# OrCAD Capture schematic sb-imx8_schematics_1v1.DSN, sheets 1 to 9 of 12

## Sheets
1 11. PCIe x1: size A; title: 11. PCIe x1; rev: 1.1; note: 8010055003
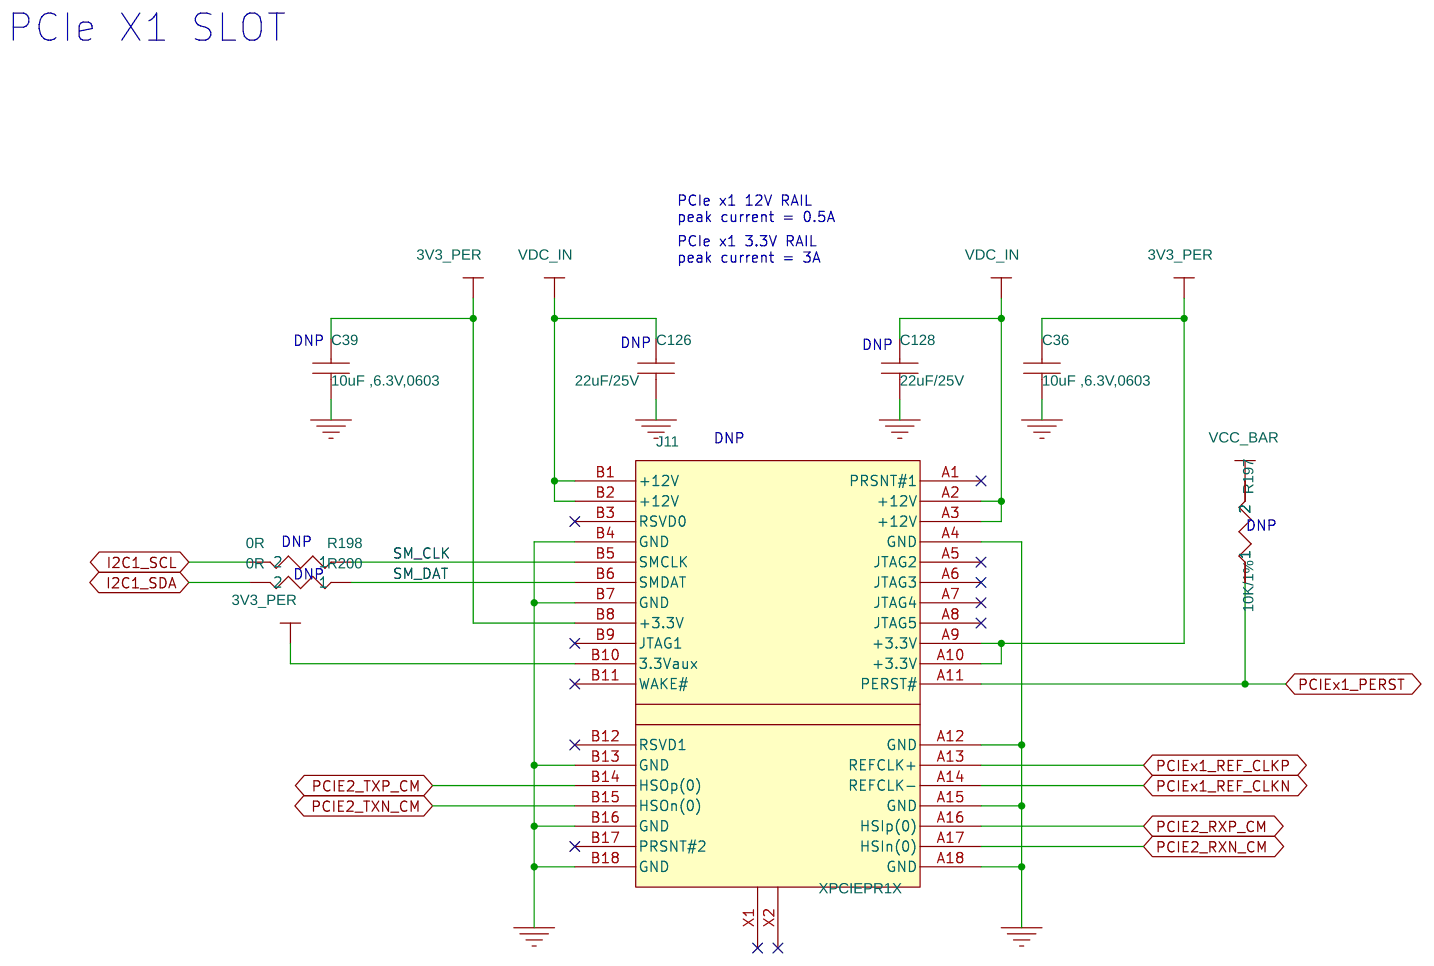
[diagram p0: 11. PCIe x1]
2 10. LVDS LCD: size A3; title: 10. LVDS LCD
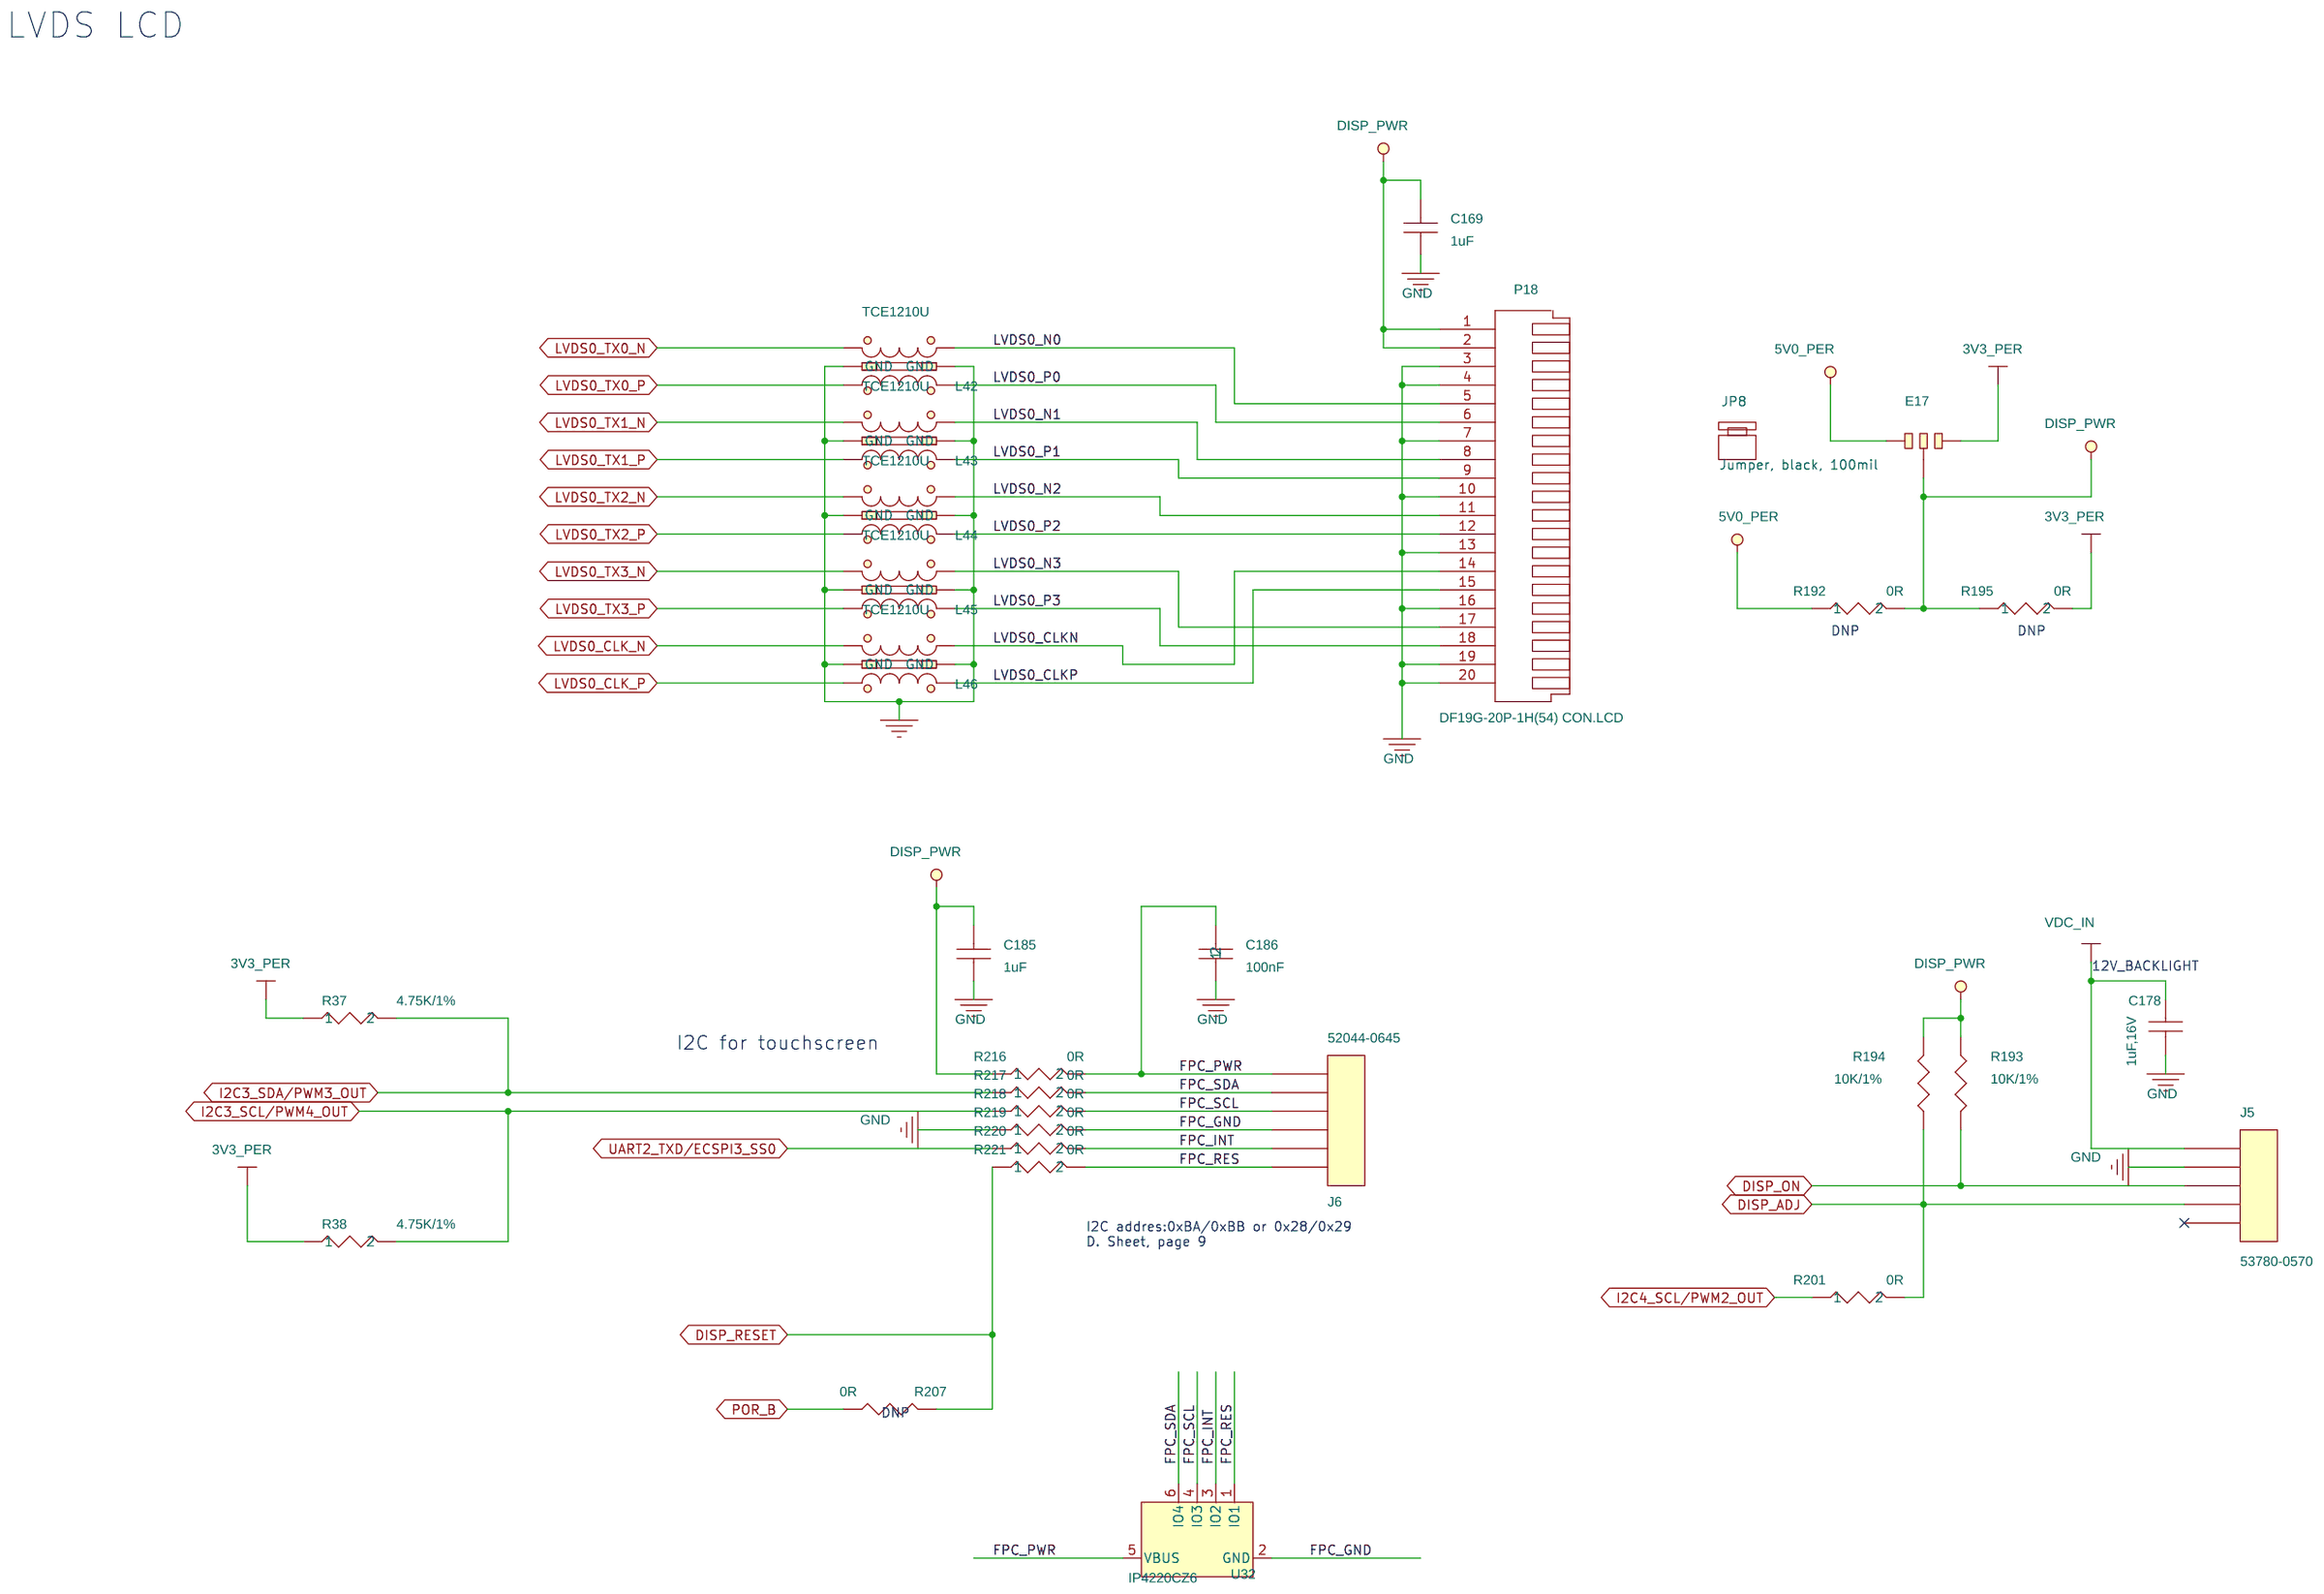
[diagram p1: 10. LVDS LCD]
3 12. Mechanics: size B; title: 12. Mechanics; note: 8000064001
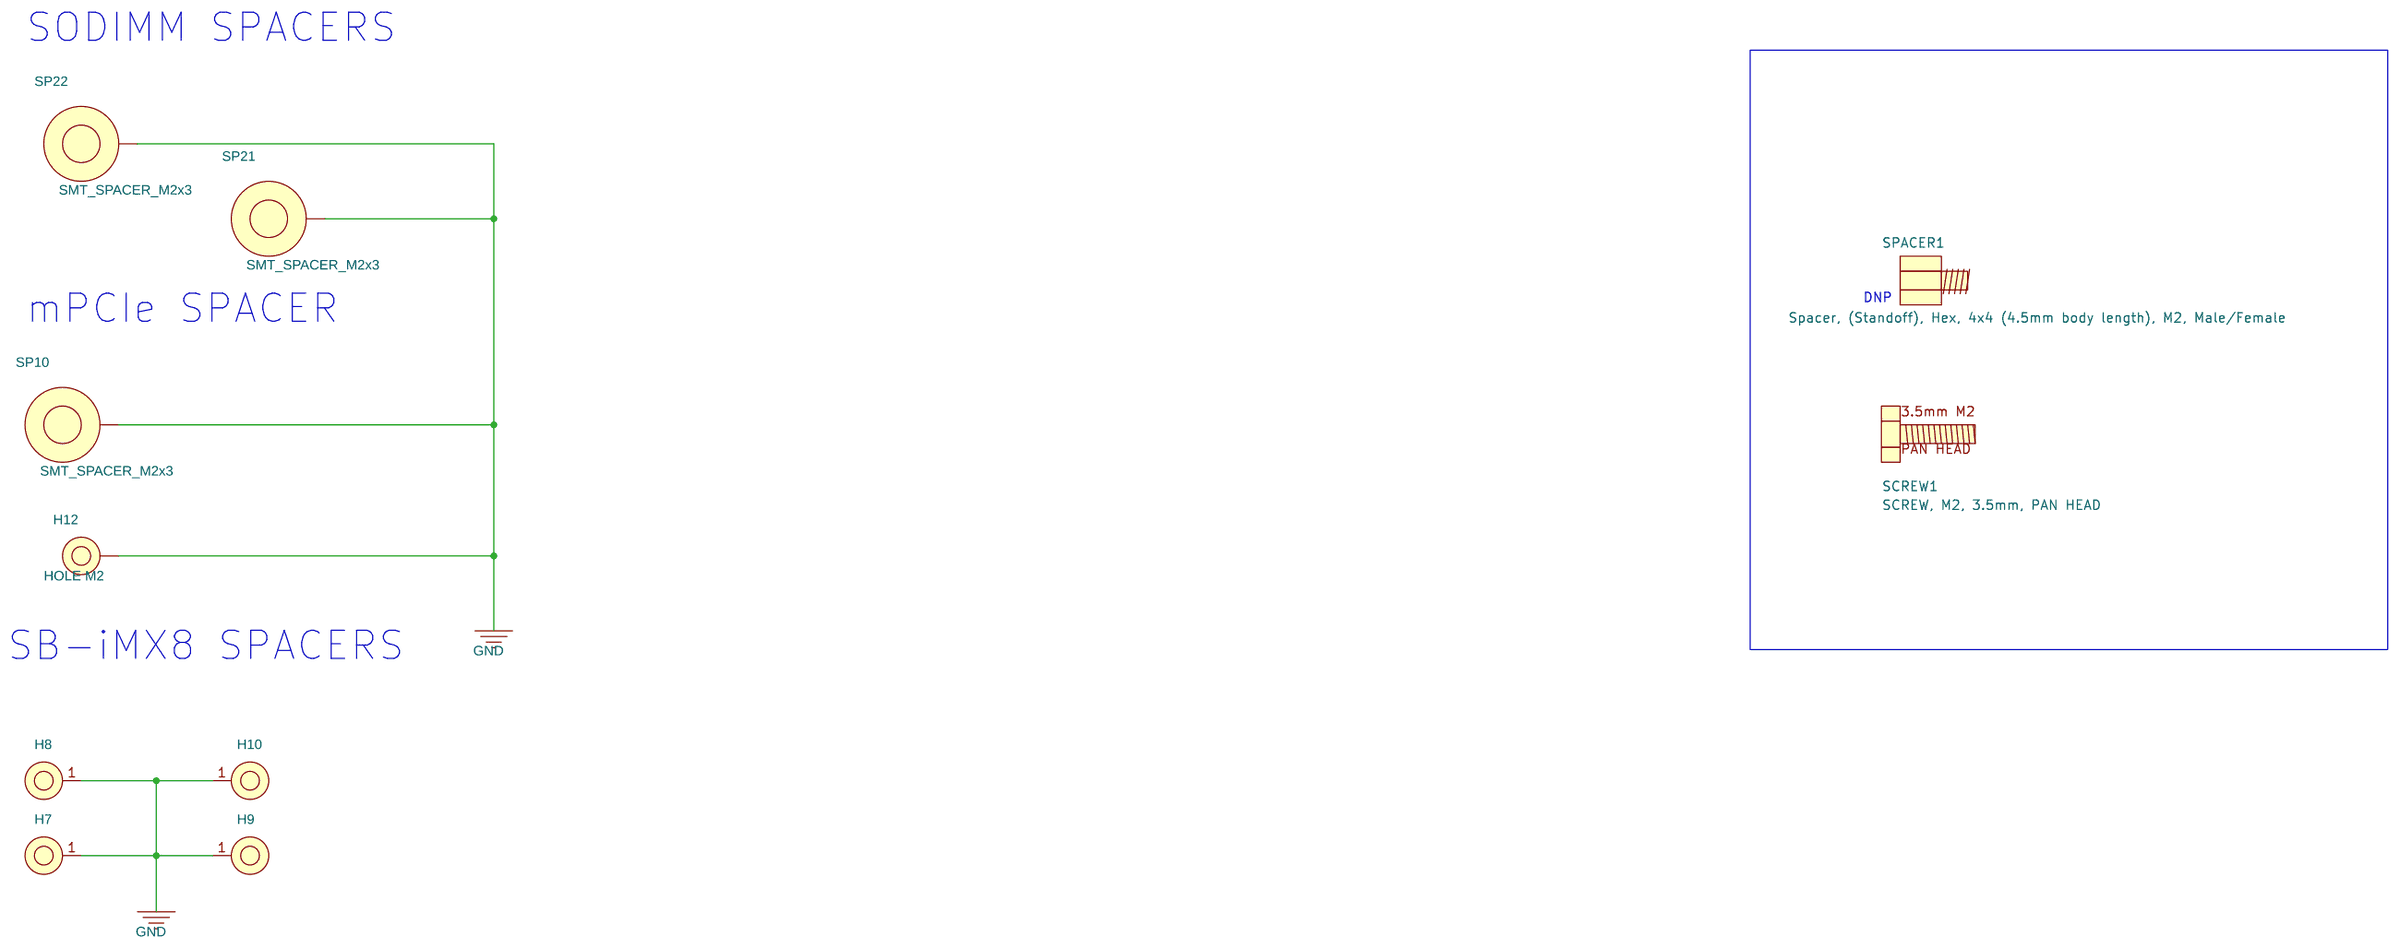
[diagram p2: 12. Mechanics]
4 01. BLOCK DIAGRAM: size C; title: 01. BLOCK DIAGRAM
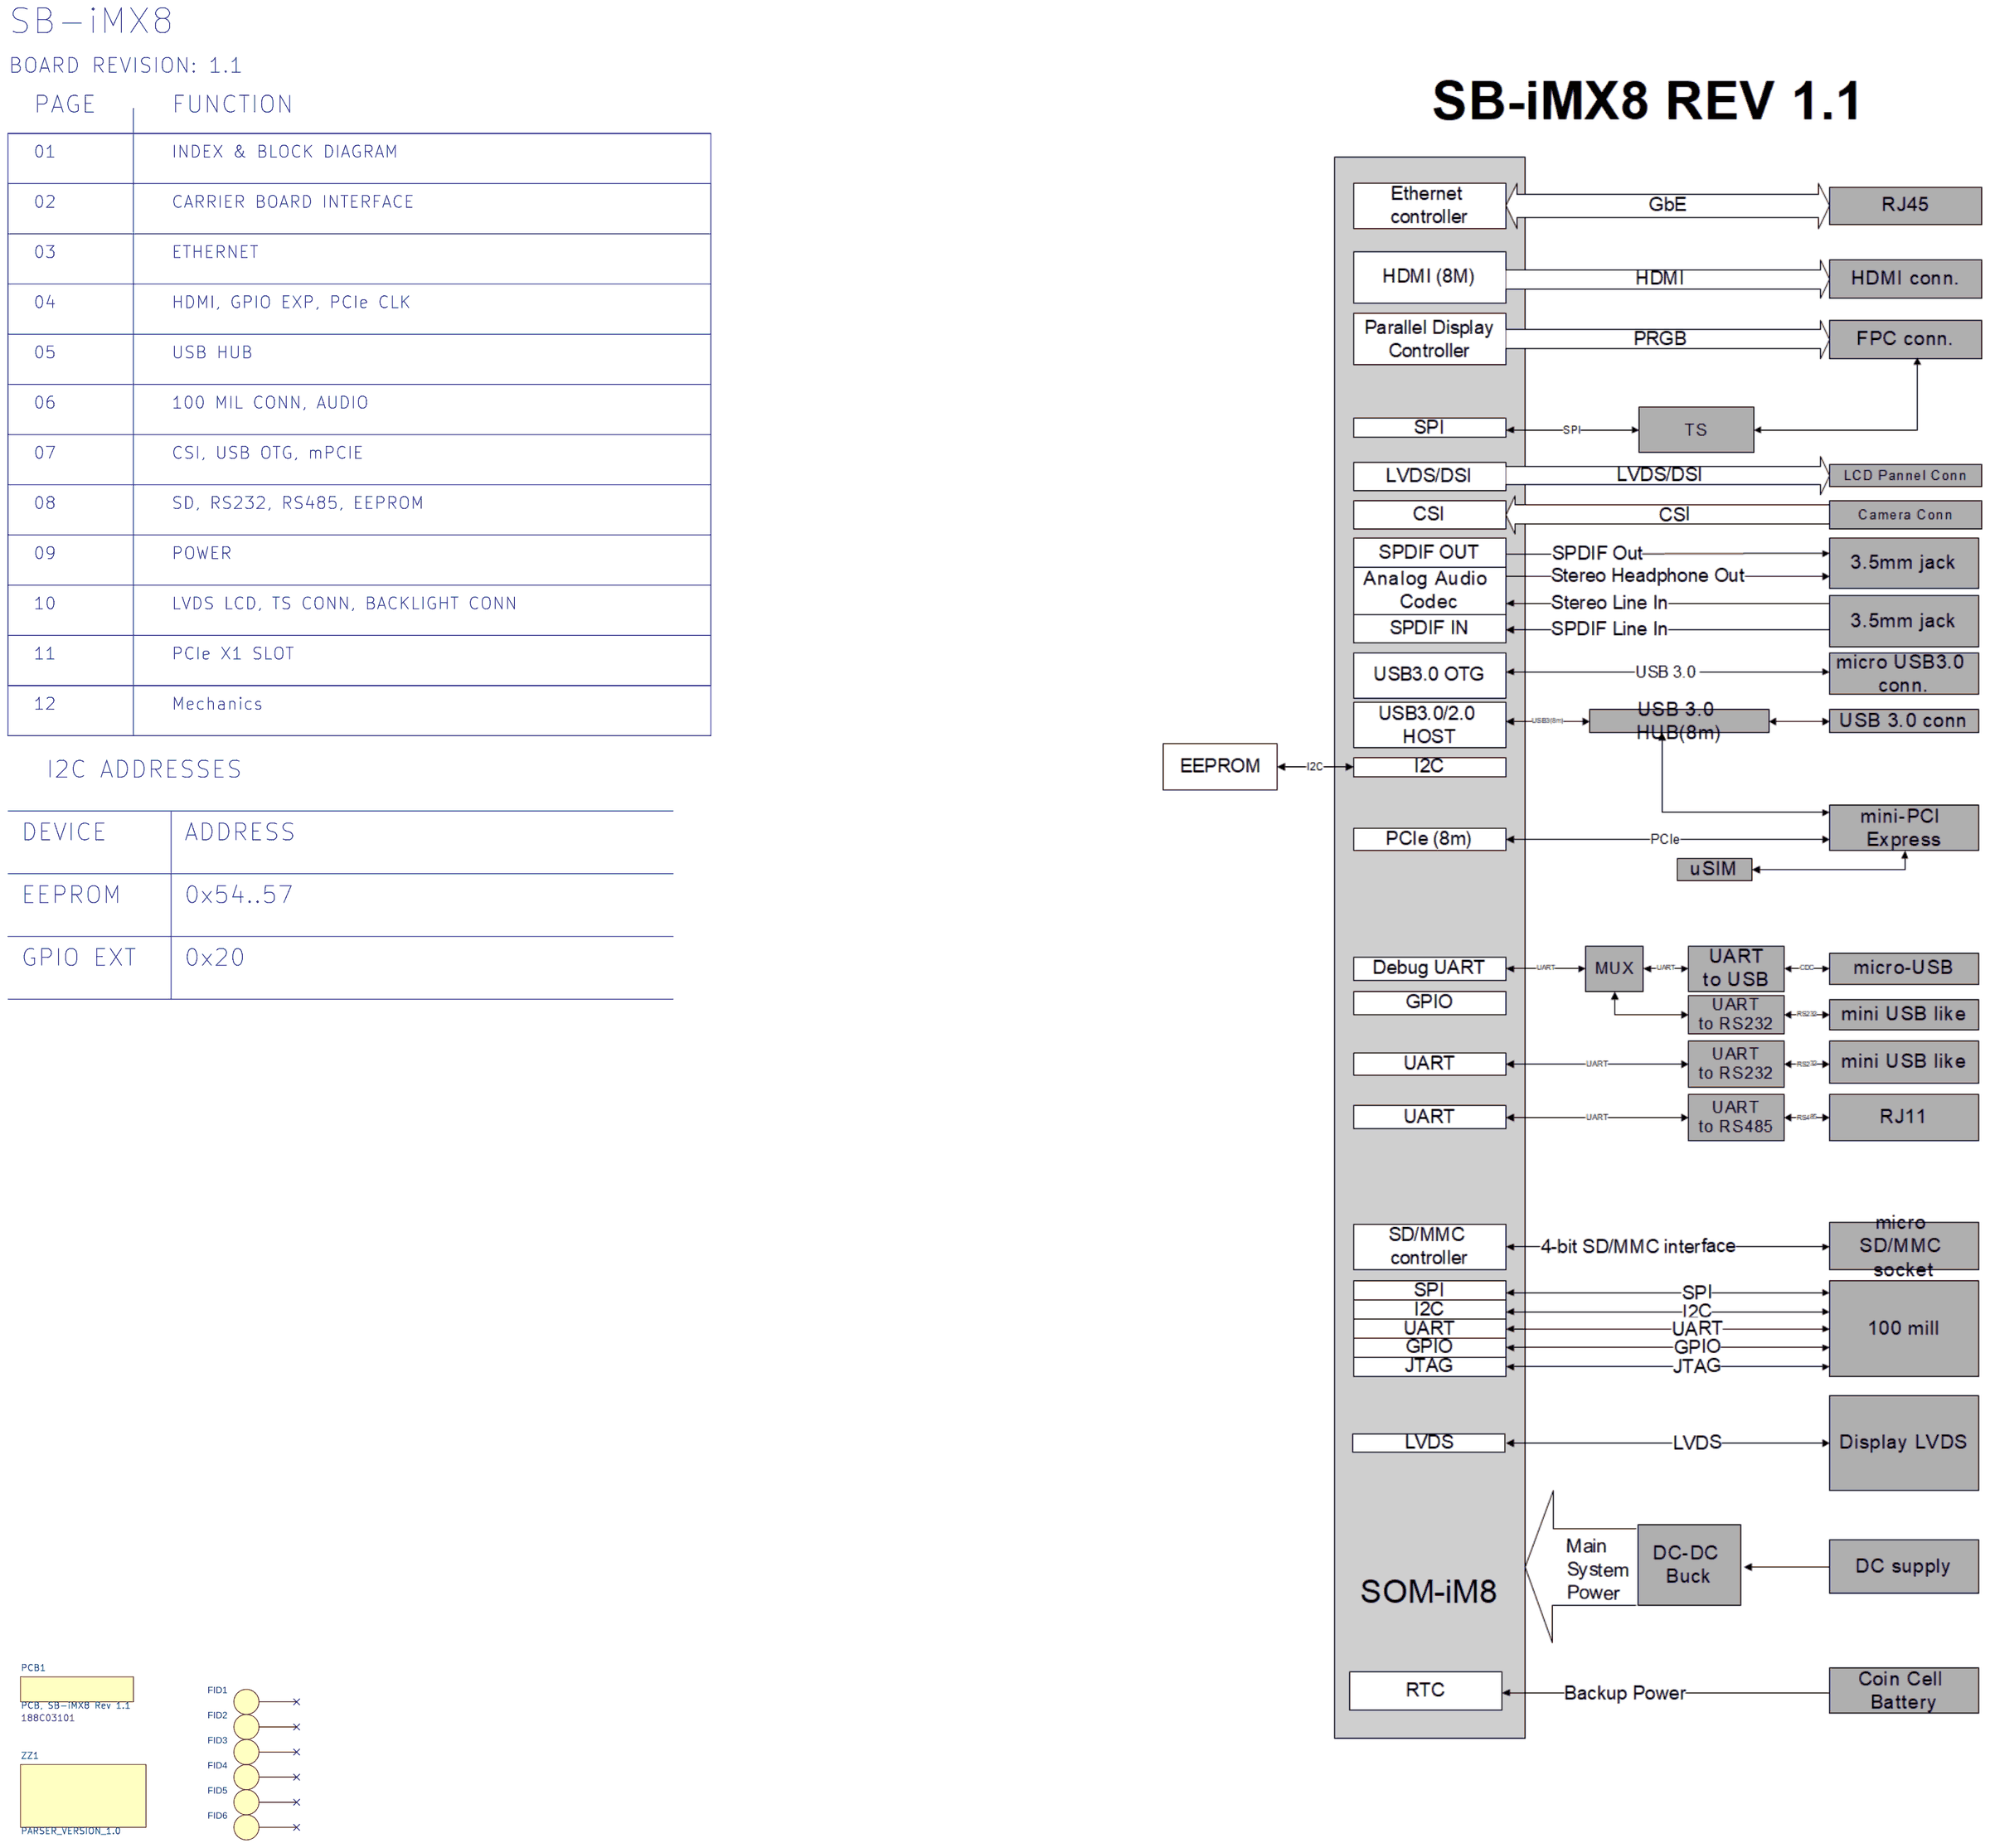
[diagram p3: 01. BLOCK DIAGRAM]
5 02. SODIMM: size C; title: 02. SODIMM; note: 8000064001
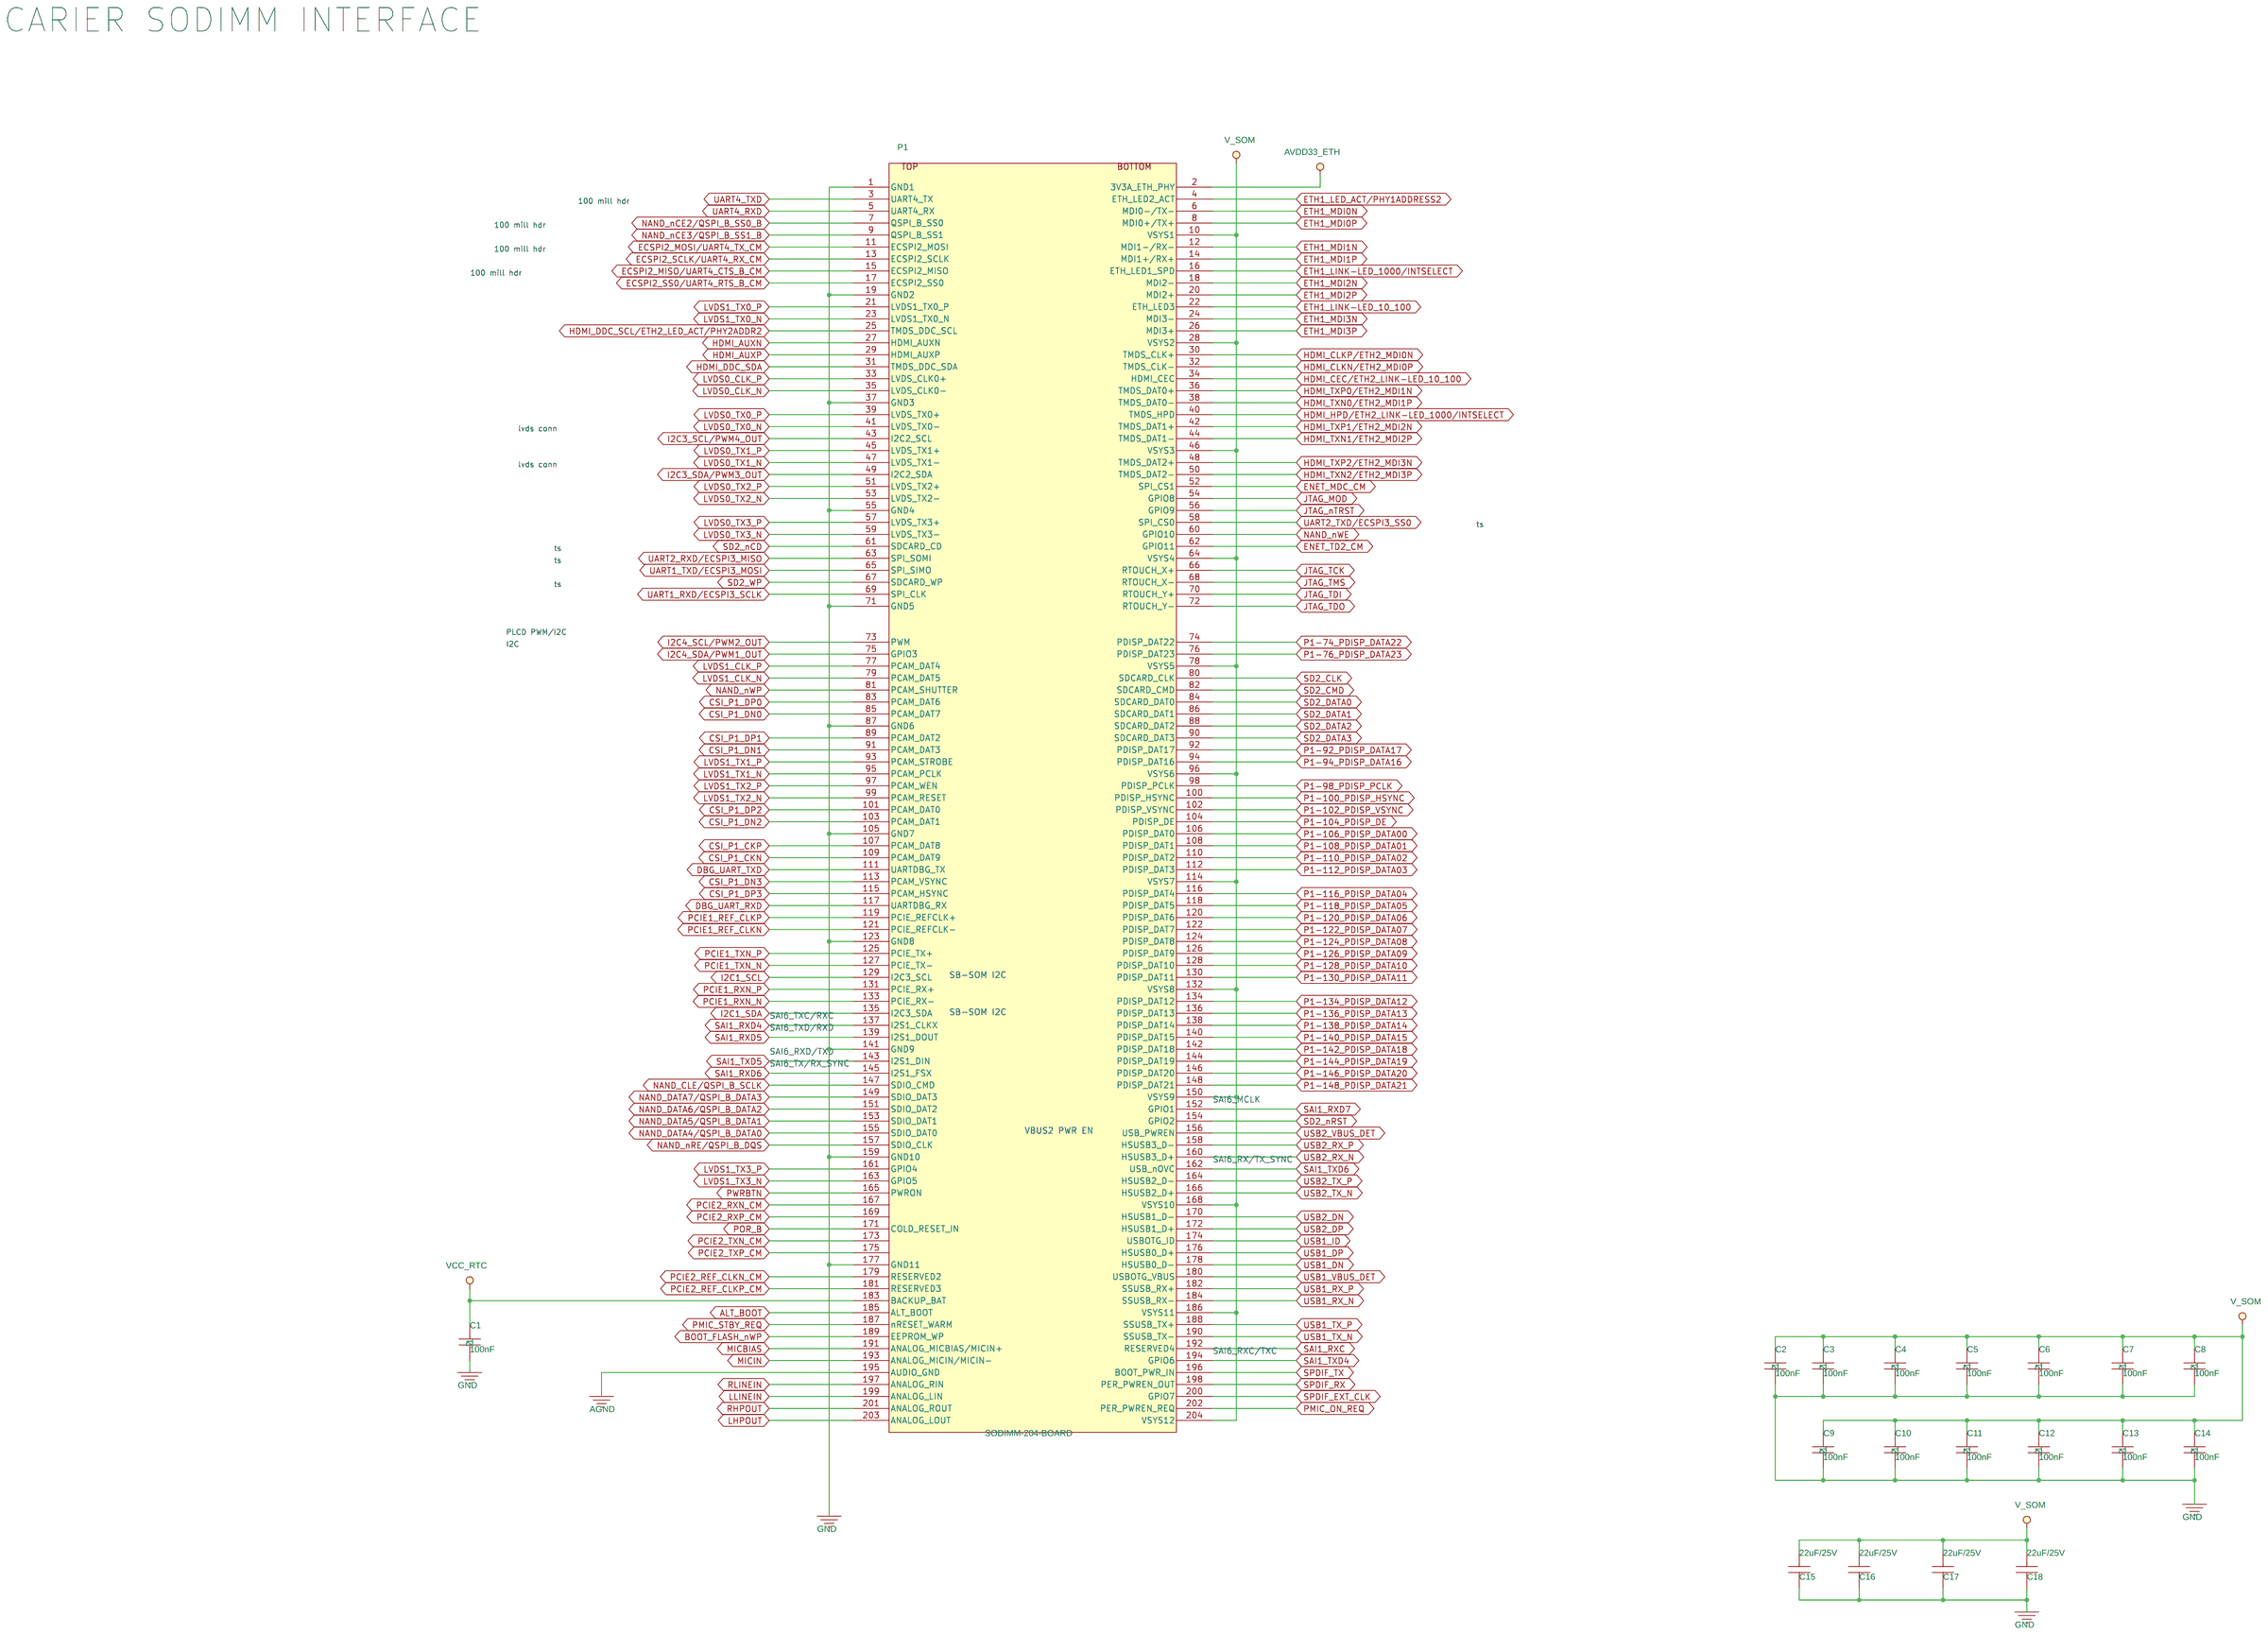
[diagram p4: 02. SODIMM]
6 03. ETHERNET 1: size B; title: 03. ETHERNET 1, LCD CONN; note: 8000064001
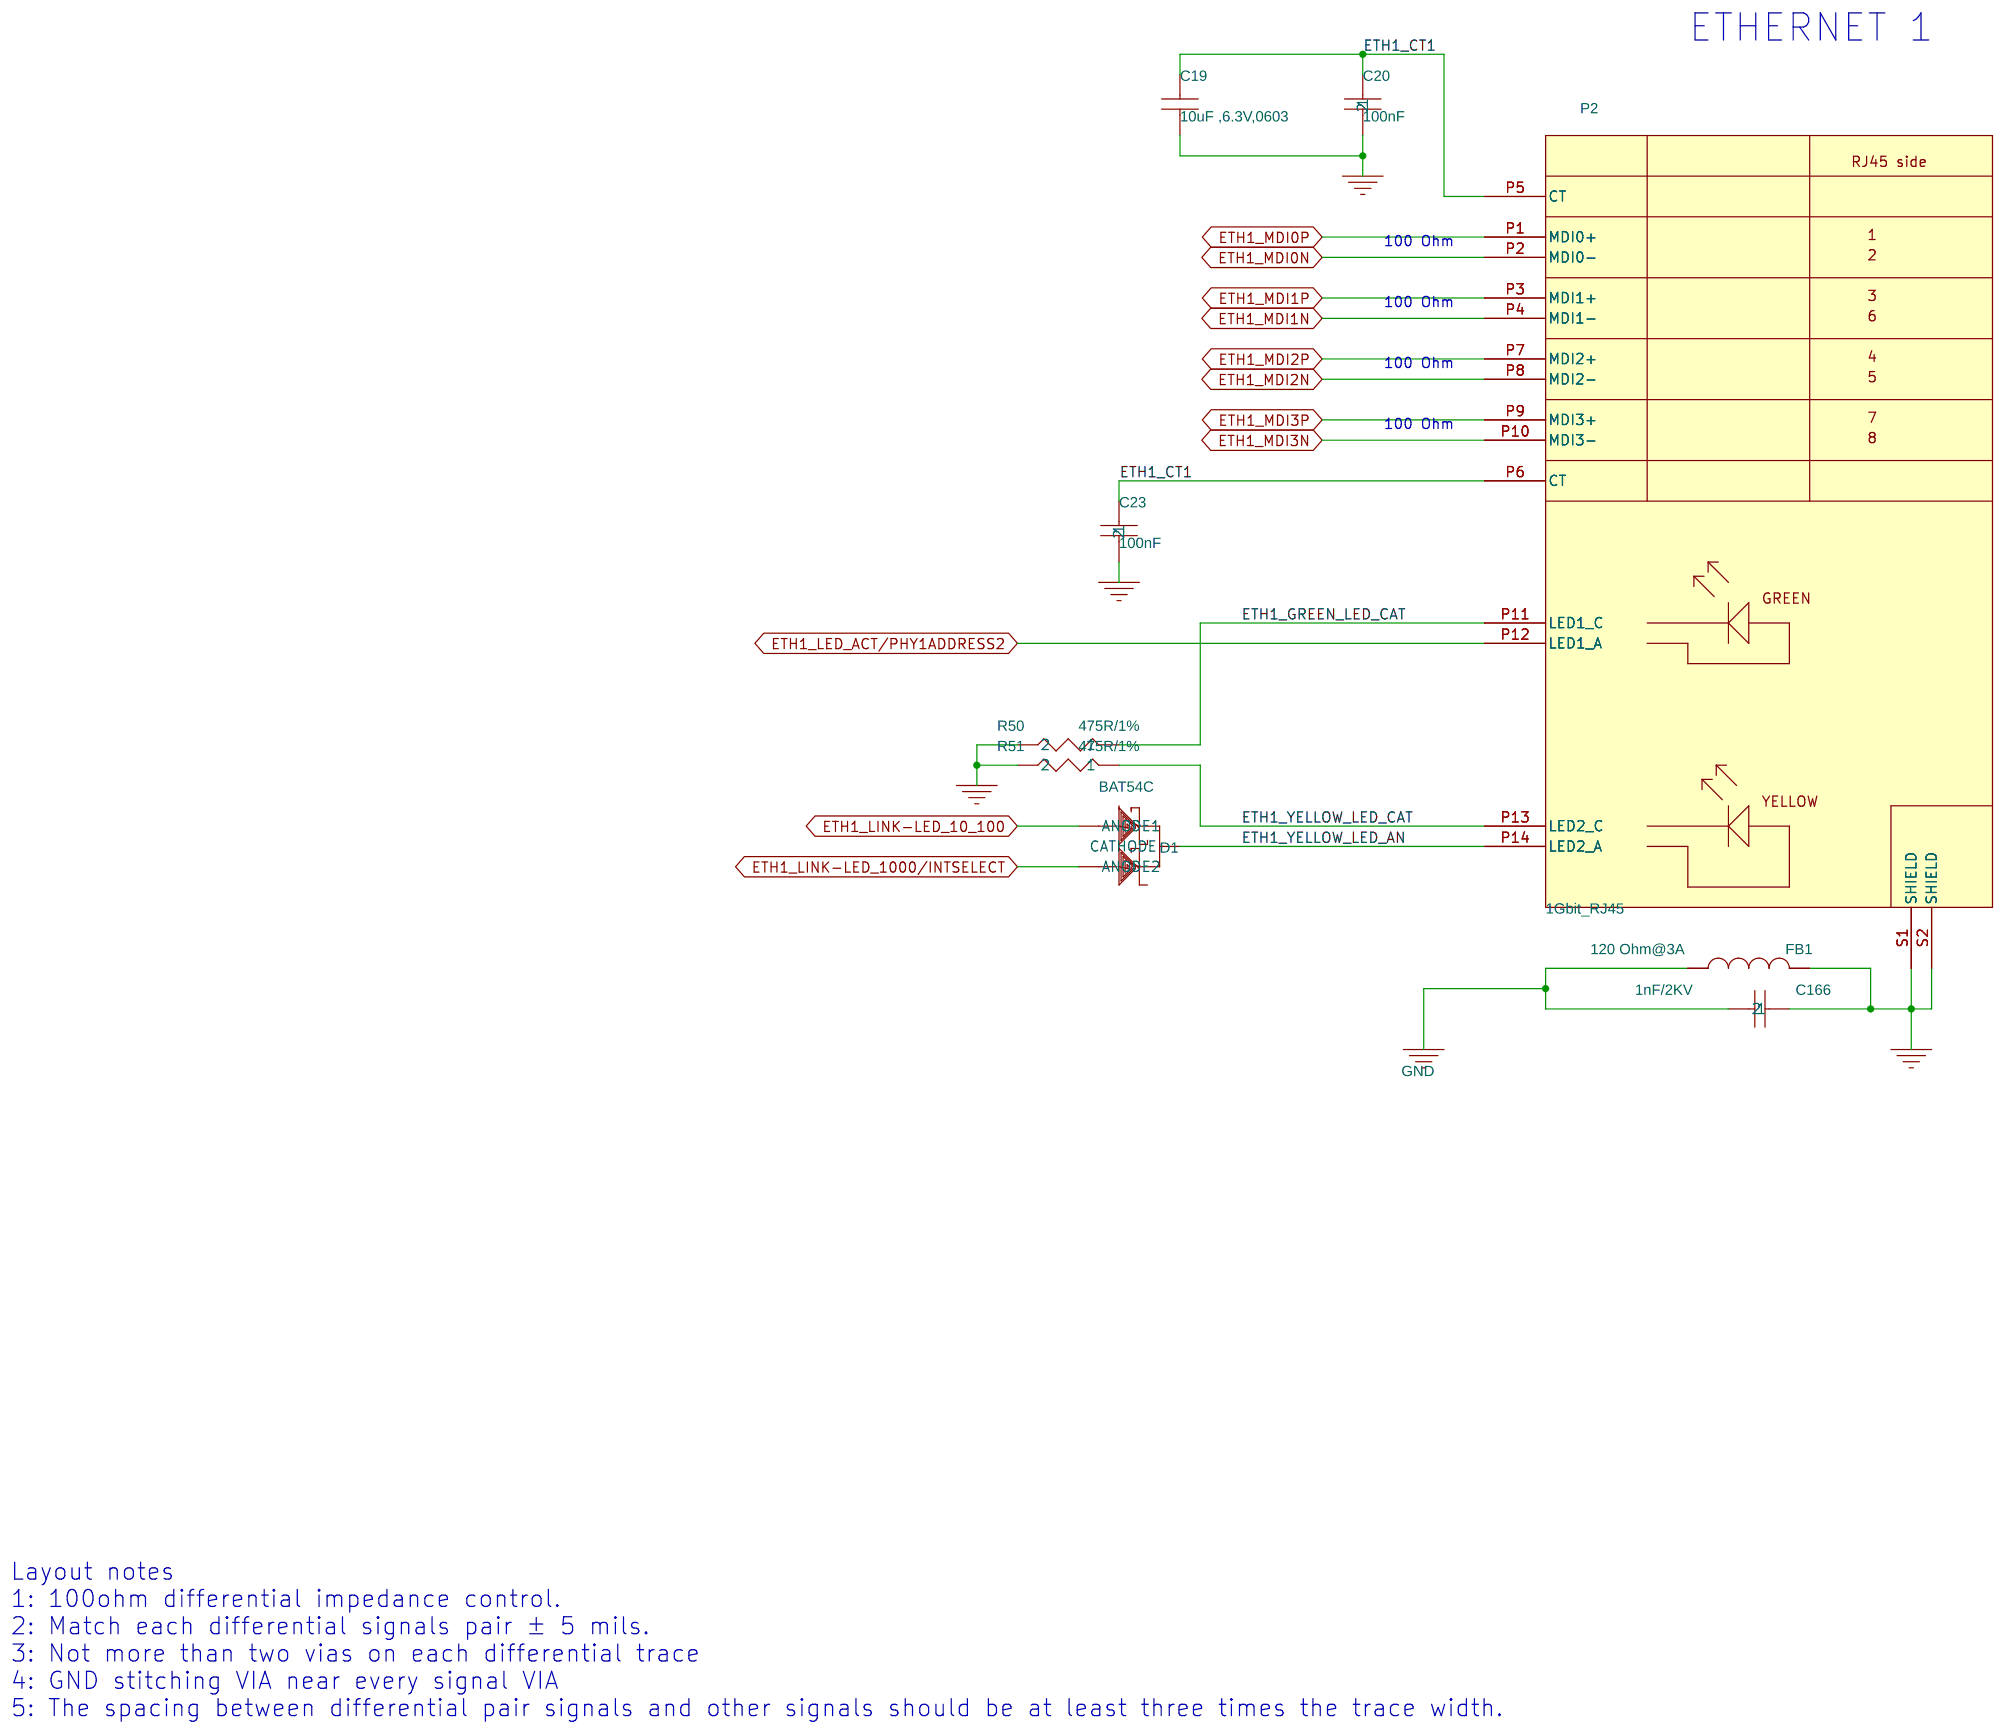
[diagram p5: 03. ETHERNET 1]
7 04. HDMI, GPIO EXT, PCIe CLK: size C; title: 04. HDMI, GPIO EXT, PCIe CLK
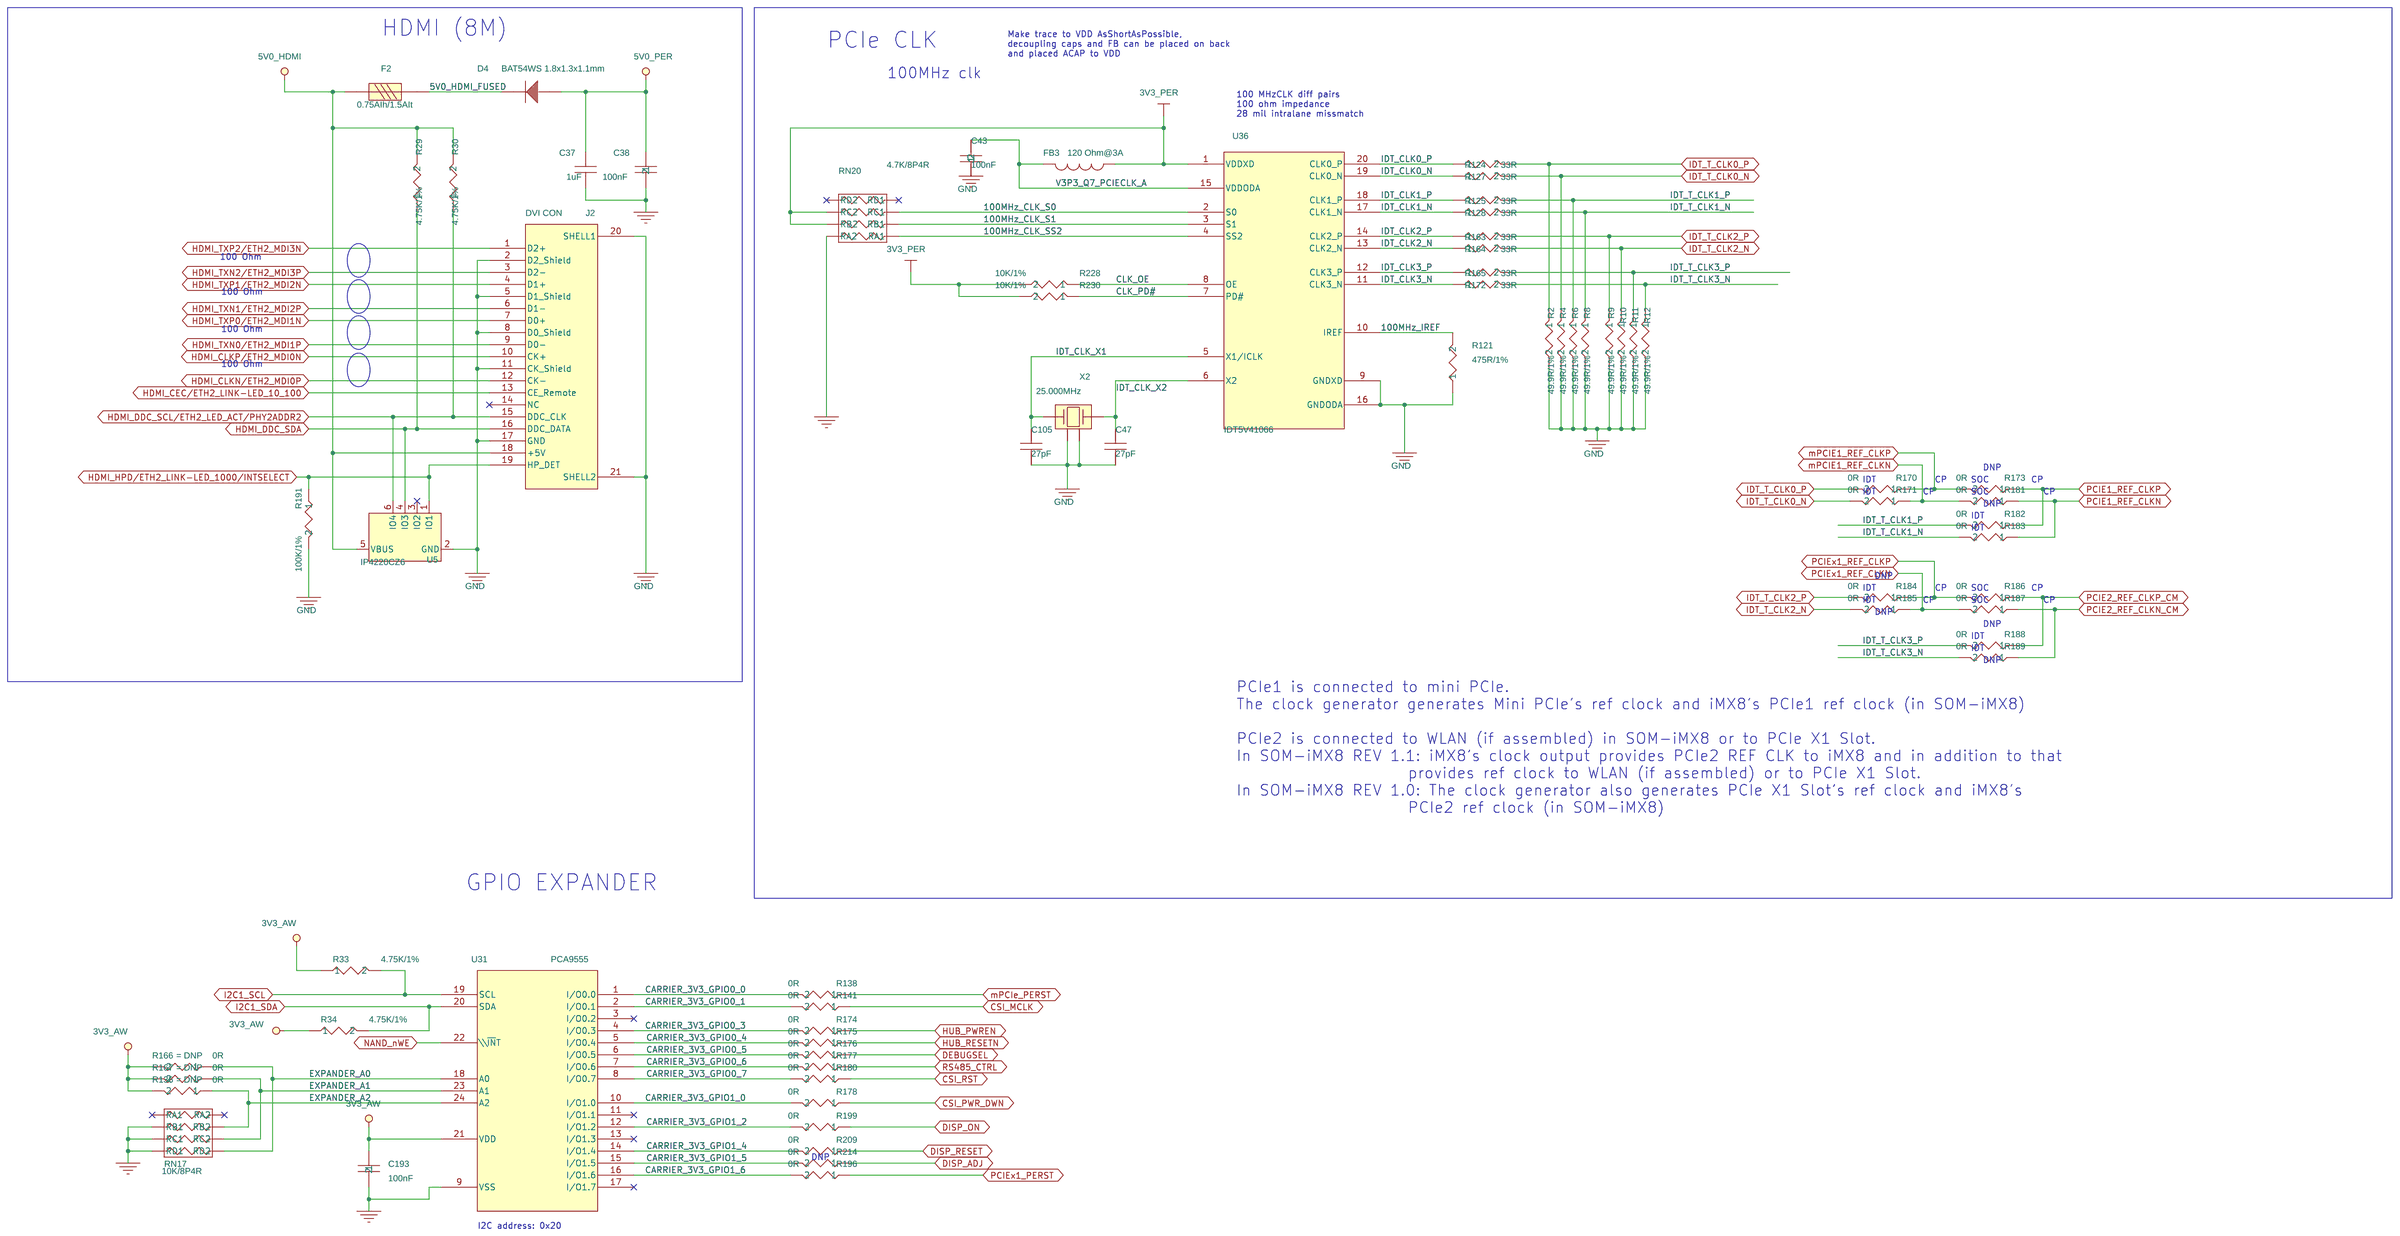
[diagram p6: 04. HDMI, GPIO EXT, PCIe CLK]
8 05. USB HUB: size B; title: 05. USB HUB, HDMI
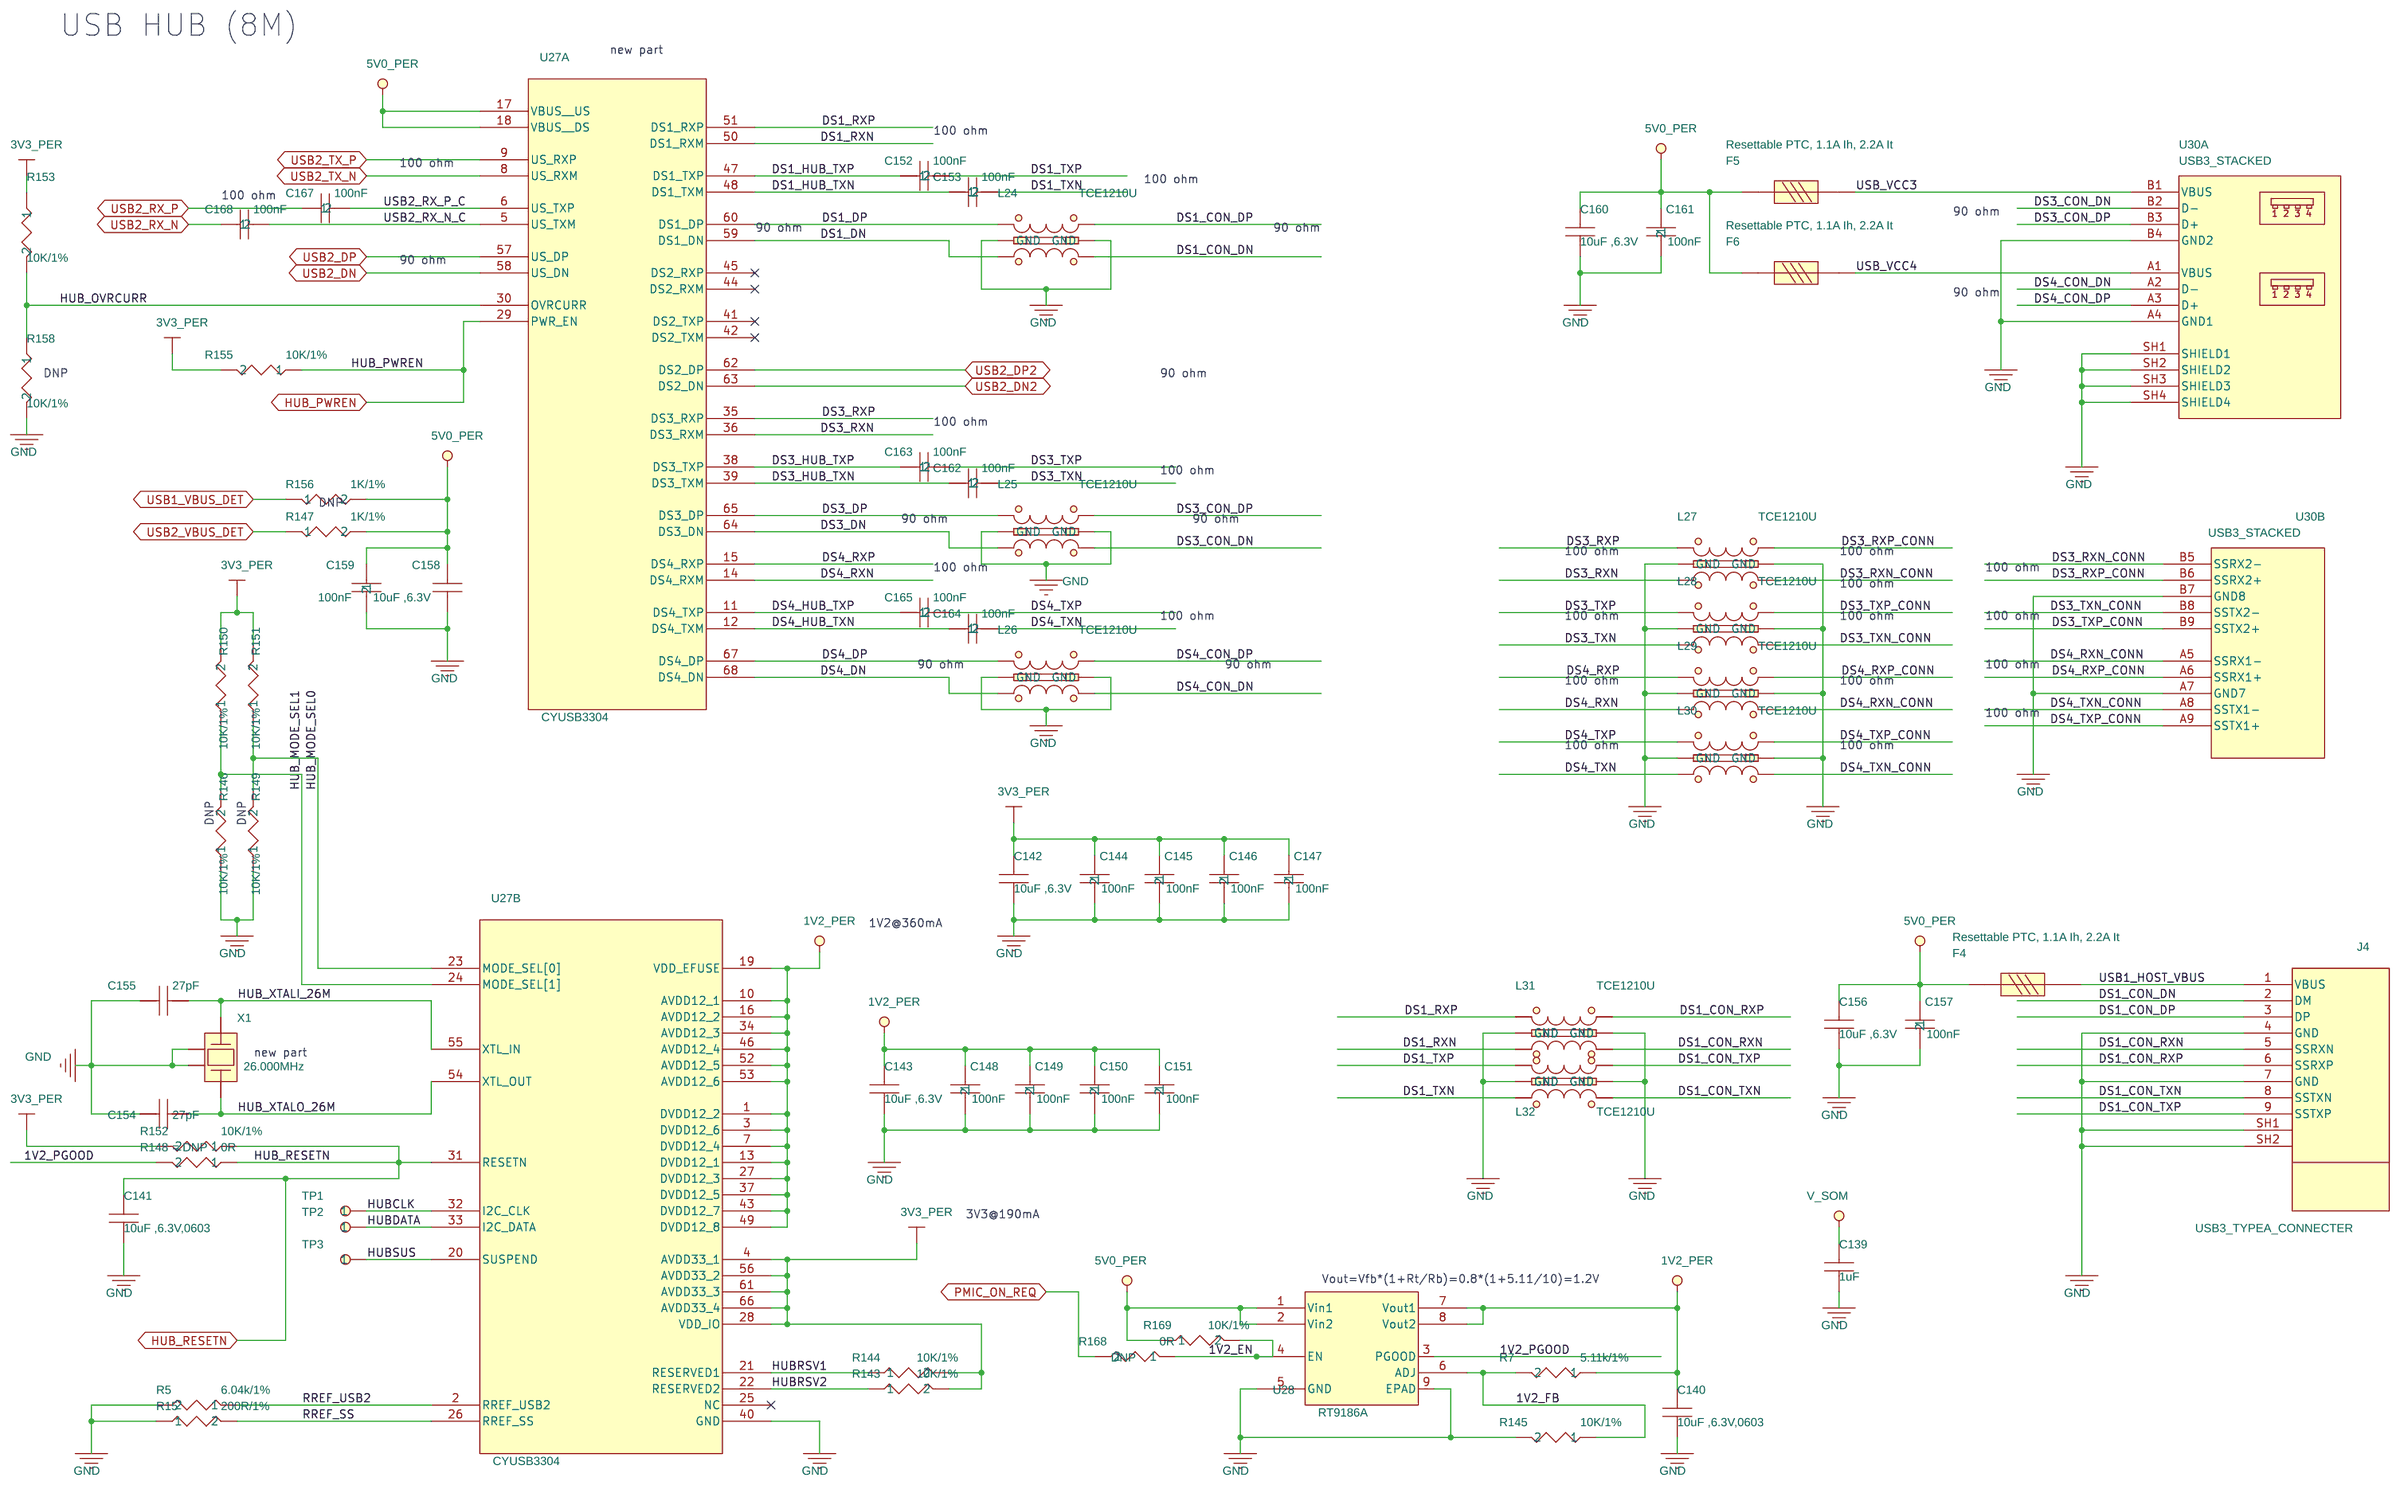
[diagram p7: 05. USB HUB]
9 06. 100 MIL CONN, AUDIO: size B; title: 06. LVDS, AUDIO
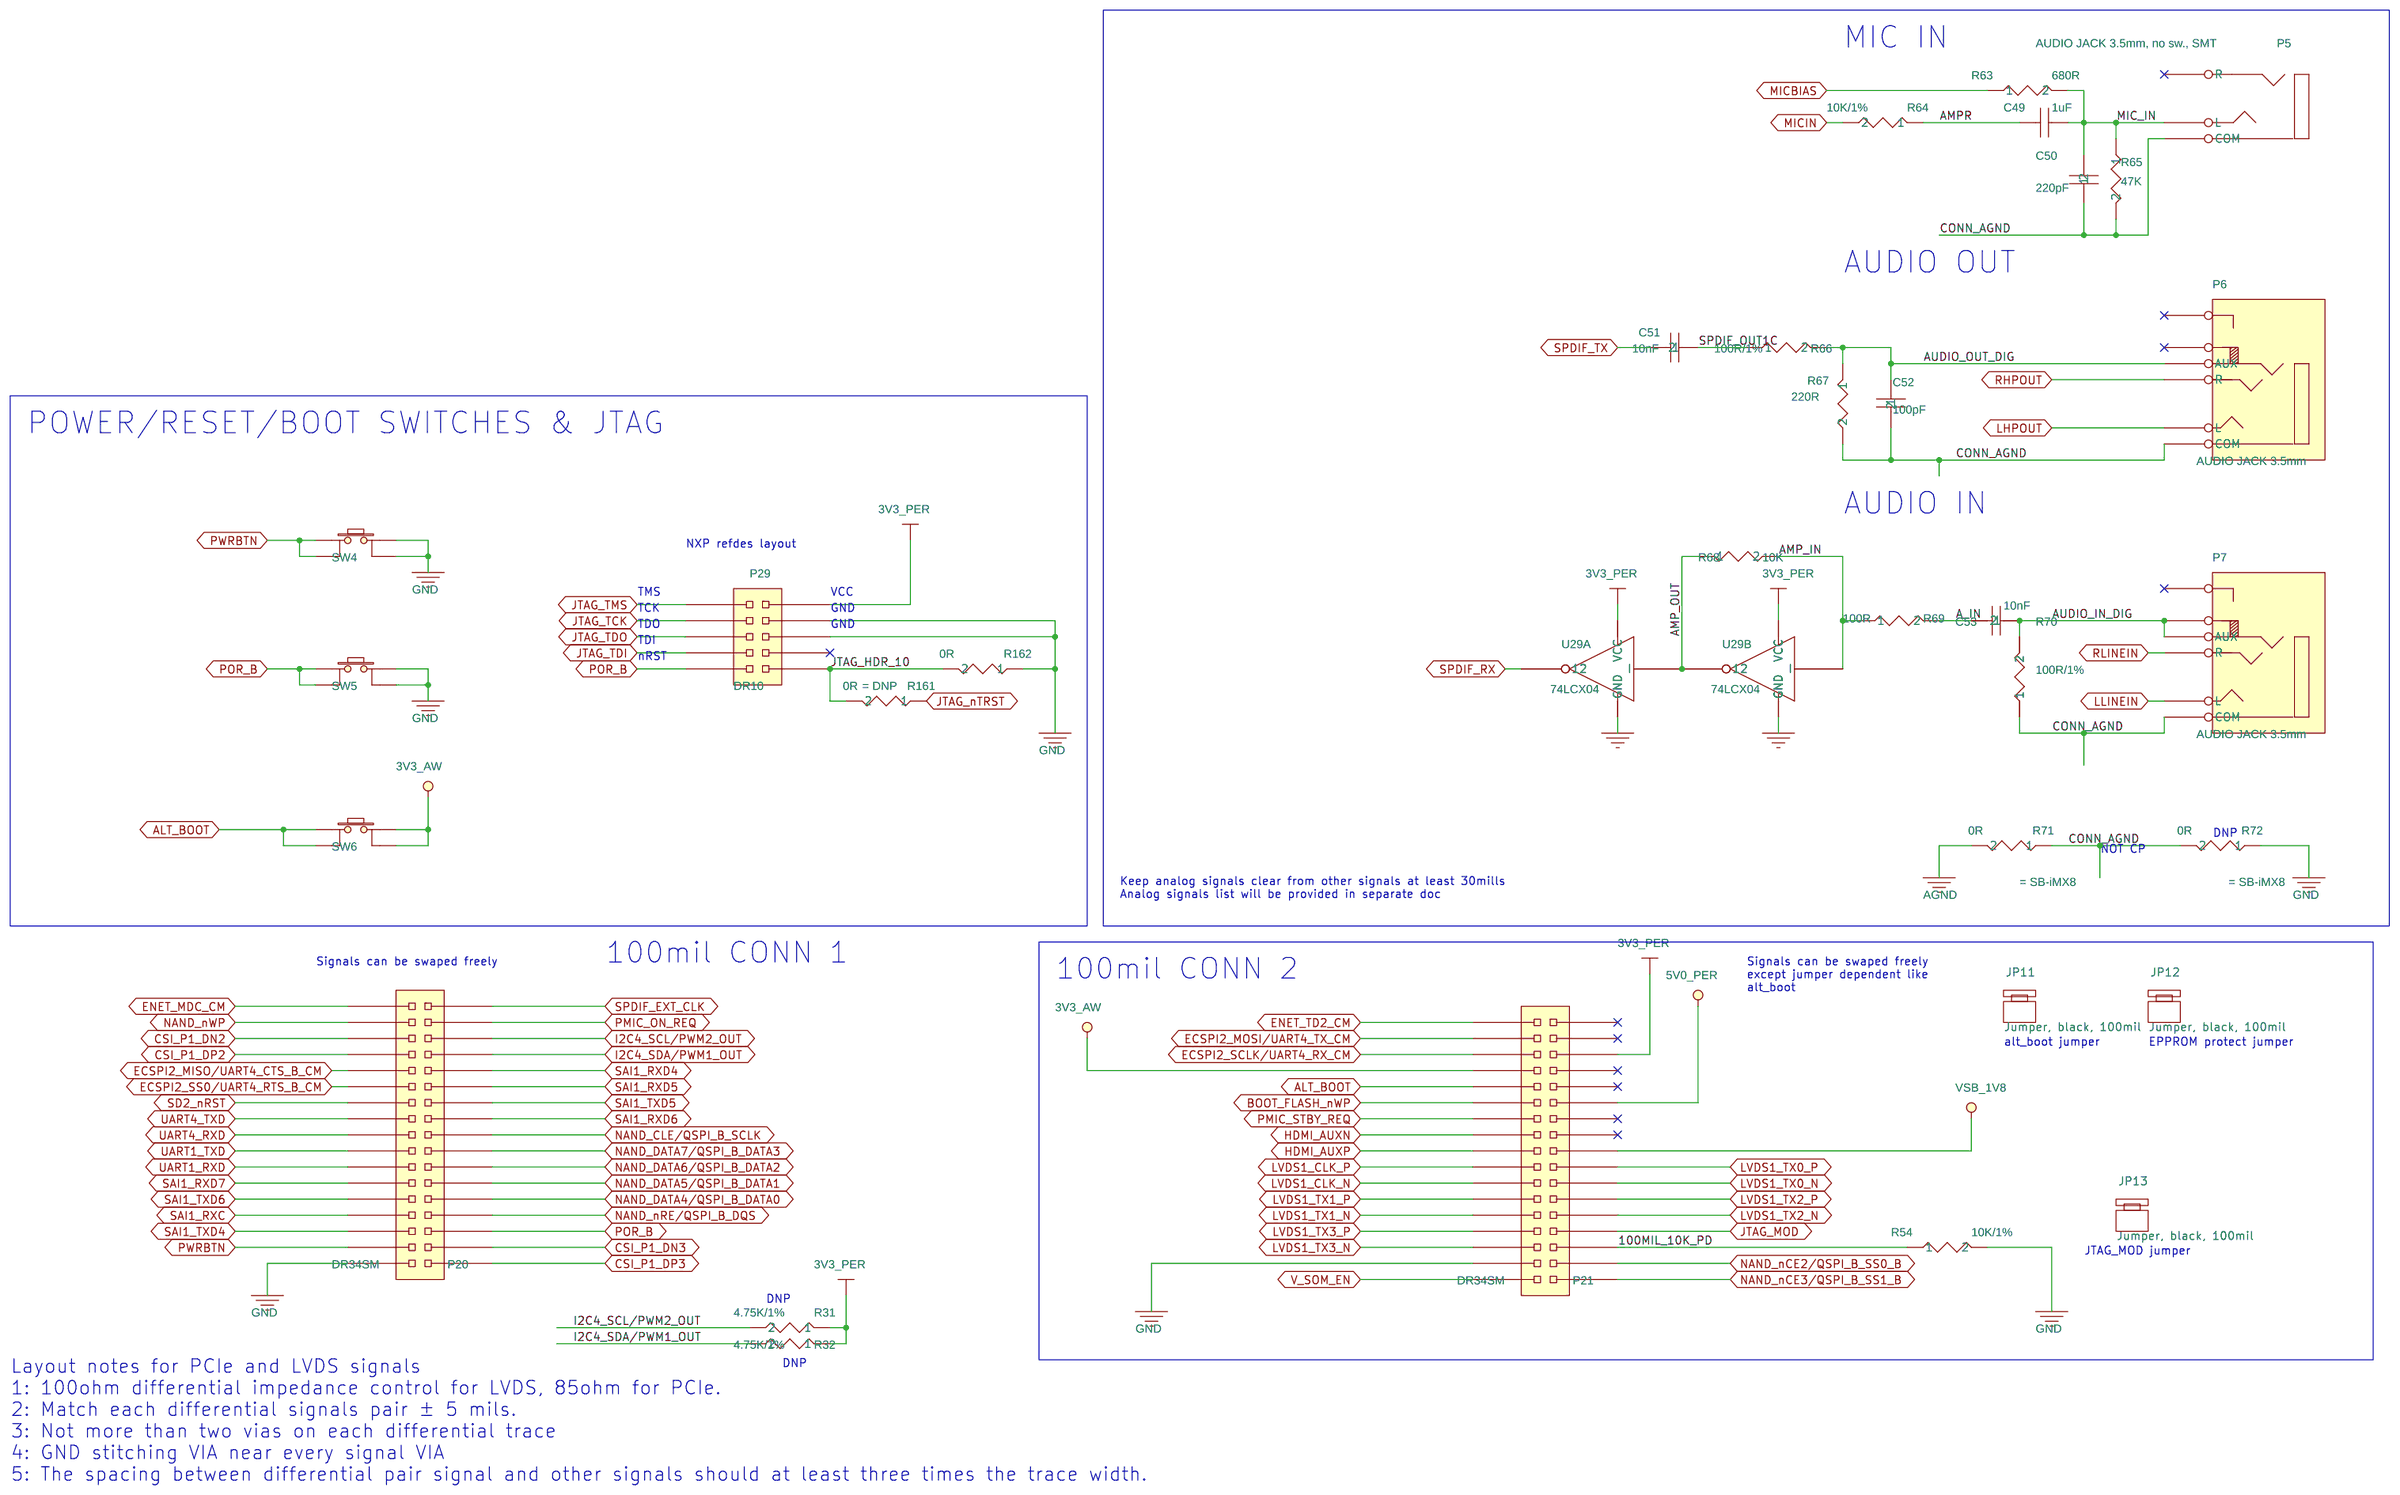
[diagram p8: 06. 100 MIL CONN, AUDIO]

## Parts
sheet 01. BLOCK DIAGRAM
FID1  FIDUCIAL  [FIDUCIAL]
FID2  FIDUCIAL  [FIDUCIAL]
FID3  FIDUCIAL  [FIDUCIAL]
FID4  FIDUCIAL  [FIDUCIAL]
FID5  FIDUCIAL  [FIDUCIAL]
FID6  FIDUCIAL  [FIDUCIAL]
PCB1  PCB, SB-iMX8 Rev 1.1
ZZ1  PARSER_VERSION_1.0
sheet 02. SODIMM
C1  100nF  [RC0402]
C2  100nF  [RC0402]
C3  100nF  [RC0402]
C4  100nF  [RC0402]
C5  100nF  [RC0402]
C6  100nF  [RC0402]
C7  100nF  [RC0402]
C8  100nF  [RC0402]
C9  100nF  [RC0402]
C10  100nF  [RC0402]
C11  100nF  [RC0402]
C12  100nF  [RC0402]
C13  100nF  [RC0402]
C14  100nF  [RC0402]
C15  22uF/25V  [C0805]
C16  22uF/25V  [C0805]
C17  22uF/25V  [C0805]
C18  22uF/25V  [C0805]
P1  SODIMM-204-BOARD  [190I20400S]
sheet 03. ETHERNET 1
C19  10uF ,6.3V,0603  [RC0603]
C20  100nF  [RC0402]
C23  100nF  [RC0402]
C166  1nF/2KV  [C1812]
D1  BAT54C  [SOT23]
FB1  120 Ohm@3A  [1206]
P2  1Gbit_RJ45  [DUSBRJ-1G]
R50  475R/1%  [RC0402]
R51  475R/1%  [RC0402]
sheet 04. HDMI, GPIO EXT, PCIe CLK
C37  1uF  [RC0402]
C38  100nF  [RC0402]
C43  100nF  [RC0402]
C47  27pF  [RC0402]
C105  27pF  [RC0402]
C193  100nF  [RC0402]
D4  BAT54WS 1.8x1.3x1.1mm  [SOD-323]
F2  0.75AIh/1.5AIt  [FUSE-1206]
FB3  120 Ohm@3A  [FB1206]
J2  DVI CON  [HDMI-A19-RASM]
R2  49.9R/1%  [RC0402]
R4  49.9R/1%  [RC0402]
R6  49.9R/1%  [RC0402]
R8  49.9R/1%  [RC0402]
R9  49.9R/1%  [RC0402]
R10  49.9R/1%  [RC0402]
R11  49.9R/1%  [RC0402]
R12  49.9R/1%  [RC0402]
R29  4.75K/1%  [RC0402]
R30  4.75K/1%  [RC0402]
R33  4.75K/1%  [RC0402]
R34  4.75K/1%  [RC0402]
R121  475R/1%  [RC0402]
R124  33R  [RC0402]
R125  33R  [RC0402]
R127  33R  [RC0402]
R128  33R  [RC0402]
R136  0R  [RC0402]
R138  0R  [RC0402]
R141  0R  [RC0402]
R163  33R  [RC0402]
R164  33R  [RC0402]
R165  33R  [RC0402]
R166  0R  [RC0402]
R167  0R  [RC0402]
R170  0R  [RC0402]
R171  0R  [RC0402]
R172  33R  [RC0402]
R173  0R  [RC0402]
R174  0R  [RC0402]
R175  0R  [RC0402]
R176  0R  [RC0402]
R177  0R  [RC0402]
R178  0R  [RC0402]
R180  0R  [RC0402]
R181  0R  [RC0402]
R182  0R  [RC0402]
R183  0R  [RC0402]
R184  0R  [RC0402]
R185  0R  [RC0402]
R186  0R  [RC0402]
R187  0R  [RC0402]
R188  0R  [RC0402]
R189  0R  [RC0402]
R191  100K/1%  [RC0402]
R196  0R  [RC0402]
R199  0R  [RC0402]
R209  0R  [RC0402]
R214  0R  [RC0402]
R228  10K/1%  [RC0402]
R230  10K/1%  [RC0402]
RN17  10K/8P4R  [RESNET8P0805]
RN20  4.7K/8P4R  [RESNET8P0805]
U5  IP4220CZ6  [SOT23-6L]
U31  PCA9555  [QFN4x4-24]
U36  IDT5V41066  [TSSOP-20]
X2  25.000MHz  [OSC3225]
sheet 05. USB HUB
C139  1uF  [RC0402]
C140  10uF ,6.3V,0603  [C0603-08]
C141  10uF ,6.3V,0603  [C0603-08]
C142  10uF ,6.3V  [C0603-08]
C143  10uF ,6.3V  [C0603-08]
C144  100nF  [RC0402]
C145  100nF  [RC0402]
C146  100nF  [RC0402]
C147  100nF  [RC0402]
C148  100nF  [RC0402]
C149  100nF  [RC0402]
C150  100nF  [RC0402]
C151  100nF  [RC0402]
C152  100nF  [RC0402]
C153  100nF  [RC0402]
C154  27pF  [RC0402]
C155  27pF  [RC0402]
C156  10uF ,6.3V  [C0603-08]
C157  100nF  [RC0402]
C158  10uF ,6.3V  [C0603-08]
C159  100nF  [RC0402]
C160  10uF ,6.3V  [C0603-08]
C161  100nF  [RC0402]
C162  100nF  [RC0402]
C163  100nF  [RC0402]
C164  100nF  [RC0402]
C165  100nF  [RC0402]
C167  100nF  [RC0402]
C168  100nF  [RC0402]
F4  Resettable PTC, 1.1A Ih, 2.2A It  [FUSE-1206]
F5  Resettable PTC, 1.1A Ih, 2.2A It  [FUSE-1206]
F6  Resettable PTC, 1.1A Ih, 2.2A It  [FUSE-1206]
J4  USB3_TYPEA_CONNECTER  [USB3_TYPEA]
L24  TCE1210U  [EMI1012-ESD]
L25  TCE1210U  [EMI1012-ESD]
L26  TCE1210U  [EMI1012-ESD]
L27  TCE1210U  [EMI1012-ESD]
L28  TCE1210U  [EMI1012-ESD]
L29  TCE1210U  [EMI1012-ESD]
L30  TCE1210U  [EMI1012-ESD]
L31  TCE1210U  [EMI1012-ESD]
L32  TCE1210U  [EMI1012-ESD]
R5  6.04k/1%  [RC0402]
R7  5.11k/1%  [RC0402]
R15  200R/1%  [RC0402]
R143  10K/1%  [RC0402]
R144  10K/1%  [RC0402]
R145  10K/1%  [RC0402]
R146  10K/1%  [RC0402]
R147  1K/1%  [RC0402]
R148  0R  [RC0402]
R149  10K/1%  [RC0402]
R150  10K/1%  [RC0402]
R151  10K/1%  [RC0402]
R152  10K/1%  [RC0402]
R153  10K/1%  [RC0402]
R155  10K/1%  [RC0402]
R156  1K/1%  [RC0402]
R158  10K/1%  [RC0402]
R168  0R  [RC0402]
R169  10K/1%  [RC0402]
TP1  TESTPOINT  [TESTPOINT]
TP2  TESTPOINT  [TESTPOINT]
TP3  TESTPOINT  [TESTPOINT]
U27  CYUSB3304  [QFN8x8-68]  (sections A,B)
U28  RT9186A  [DFN3x3-8]
U30  USB3_STACKED  [USB3-2XA-TH]  (sections A,B)
X1  26.000MHz  [OSC3225]
sheet 06. 100 MIL CONN, AUDIO
C49  1uF  [RC0402]
C50  220pF  [RC0603]
C51  10nF  [RC0402]
C52  100pF  [RC0402]
C53  10nF  [RC0402]
JP11  Jumper, black, 100mil
JP12  Jumper, black, 100mil
JP13  Jumper, black, 100mil
P5  AUDIO JACK 3.5mm, no sw., SMT  [AJ35-3P-SM]
P6  AUDIO JACK 3.5mm  [AJ35-4P-SW-SM]
P7  AUDIO JACK 3.5mm  [AJ35-4P-SW-SM]
P20  DR34SM  [2X17SMHDR]
P21  DR34SM  [2X17SMHDR]
P29  DR10  [2X5THHDR]
R31  4.75K/1%  [RC0402]
R32  4.75K/1%  [RC0402]
R54  10K/1%  [RC0402]
R63  680R  [RC0402]
R64  10K/1%  [RC0402]
R65  47K  [RC0402]
R66  100R/1%  [RC0402]
R67  220R  [RC0402]
R68  10K  [RC0402]
R69  100R  [RC0402]
R70  100R/1%  [RC0402]
R71  0R  [RC0402]
R72  0R  [RC0402]
R161  0R  [RC0402]
R162  0R  [RC0402]
SW4  PushB  [TACTSW6x6SM]
SW5  PushB  [TACTSW6x6SM]
SW6  PushB  [TACTSW6x6SM]
U29  74LCX04  [TSSOP-14]  (sections A,B)
sheet 10. LVDS LCD
C169  1uF  [RC0402]
C178  1uF,16V  [RC0402]
C185  1uF  [RC0402]
C186  100nF  [RC0402]
E17  JP3  [1X3THHDR]
J5  53780-0570  [1x5W2B1_25RASM]
J6  52044-0645  [FPC125TH06]
JP8  Jumper, black, 100mil
L42  TCE1210U  [EMI1012-ESD]
L43  TCE1210U  [EMI1012-ESD]
L44  TCE1210U  [EMI1012-ESD]
L45  TCE1210U  [EMI1012-ESD]
L46  TCE1210U  [EMI1012-ESD]
P18  DF19G-20P-1H(54) CON.LCD  [1x20W2B1RASM]
R37  4.75K/1%  [RC0402]
R38  4.75K/1%  [RC0402]
R192  0R  [RC0402]
R193  10K/1%  [RC0402]
R194  10K/1%  [RC0402]
R195  0R  [RC0402]
R201  0R  [RC0402]
R207  0R  [RC0402]
R216  0R  [RC0402]
R217  0R  [RC0402]
R218  0R  [RC0402]
R219  0R  [RC0402]
R220  0R  [RC0402]
R221  0R  [RC0402]
U32  IP4220CZ6  [SOT23-6L]
sheet 11. PCIe x1
C36  10uF ,6.3V,0603  [RC0603]
C39  10uF ,6.3V,0603  [RC0603]
C126  22uF/25V  [C0805]
C128  22uF/25V  [C0805]
J11  XPCIEPR1X  [PCIe36P1MMSM]
R197  10K/1%  [RC0402]
R198  0R  [RC0402]
R200  0R  [RC0402]
sheet 12. Mechanics
H7  MechHole  [M3PAD]
H8  MechHole  [M3PAD]
H9  MechHole  [M3PAD]
H10  MechHole  [M3PAD]
H12  HOLE M2  [M2PAD]
SCREW1  SCREW, M2, 3.5mm, PAN HEAD  [NONE]
SP10  SMT_SPACER_M2x3  [MINIPCIE-4-Spacer]
SP21  SMT_SPACER_M2x3  [MINIPCIE-4-Spacer]
SP22  SMT_SPACER_M2x3  [MINIPCIE-4-Spacer]
SPACER1  Spacer, (Standoff), Hex, 4x4 (4.5mm body length), M2, Male/Female  [NONE]

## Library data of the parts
FID1-FID6 = TESTPOINT_2: CLABCONF0: = DNP
PCB1 = PCB,_EM-X270_Rev_1_0.1: CLABCONF0: = SB-iMX8; P/N: 188C03101
ZZ1 = PARSER_VERSION_1_1.0: CLABCONF0: =DNP
C1 C146 C193 = 100nF,_10V,_X7R,_10%,_0402_1: CLABCONF0: = SB-iMX8
C2 C152 = 100nF,_10V,_X7R,_10%,_0402_7: CLABCONF0: = SB-iMX8
C3 C153 = 100nF,_10V,_X7R,_10%,_0402_9: CLABCONF0: = SB-iMX8
C4 C151 = 100nF,_10V,_X7R,_10%,_0402_11: CLABCONF0: = SB-iMX8
C5 C159 = 100nF,_10V,_X7R,_10%,_0402_13: CLABCONF0: = SB-iMX8
C6 C147 = 100nF,_10V,_X7R,_10%,_0402_2: CLABCONF0: = SB-iMX8
C7 C164 = 100nF,_10V,_X7R,_10%,_0402_4: CLABCONF0: = SB-iMX8
C8 C149 = 100nF,_10V,_X7R,_10%,_0402_6: CLABCONF0: = SB-iMX8
C9 C165 = 100nF,_10V,_X7R,_10%,_0402_10: CLABCONF0: = SB-iMX8
C10 C43 C145 C186 = 100nF,_10V,_X7R,_10%,_0402: CLABCONF0: = SB-iMX8
C11 C157 = 100nF,_10V,_X7R,_10%,_0402_12: CLABCONF0: = SB-iMX8
C12 C161 = 100nF,_10V,_X7R,_10%,_0402_3: CLABCONF0: = SB-iMX8
C13 C148 = 100nF,_10V,_X7R,_10%,_0402_5: CLABCONF0: = SB-iMX8
C14 C150 = 100nF,_10V,_X7R,_10%,_0402_8: CLABCONF0: = SB-iMX8
C15 = Cap.,22uF,25V,_0805: CLABCONF0: = SB-iMX8
C16 = Cap.,22uF,25V,_0805_1: CLABCONF0: = SB-iMX8
C17 = Cap.,22uF,25V,_0805_2: CLABCONF0: = SB-iMX8
C18 = Cap.,22uF,25V,_0805_3: CLABCONF0: = SB-iMX8
P1 = SODIMM-204_1: CLABCONF0: = SB-iMX8
C19 = Cap.,10uF,6.3V,0603,X5R: CLABCONF0: = SB-iMX8
C20 = 100nF,_10V,_X7R,_10%,_0402: CLABCONF0: = SB-iMX8; Group: LAN2
C23 = 100nF,_10V,_X7R,_10%,_0402_1: CLABCONF0: = SB-iMX8; Group: LAN2
C166 = 1nF,_2KV,SMD_1812,_X7R,_10%: CLABCONF0: = SB-iMX8
D1 = BAT54C: CLABCONF0: = SB-iMX8
FB1 FB3 = Ferrite_bead_,_120_Ohm@3A: CLABCONF0: = SB-iMX8
P2 = Con_0.,1GBit_RJ45,_short: CLABCONF0: = SB-iMX8
R50 = 475R_1%,_0402_1: CLABCONF0: = SB-iMX8
R51 R121 = 475R_1%,_0402: CLABCONF0: = SB-iMX8
C37 C49 C139 C169 C185 = 1uF,X5R,6.3V,0402: CLABCONF0: = SB-iMX8
C38 = 100nF,_10V,_X7R,_10%,_0402_2: CLABCONF0: = SB-iMX8; Group: LAN2
C47 C105 C154 C155 = 27pF,_50V,_X7R,_10%,_0402: CLABCONF0: = SB-iMX8; P/N: 151D27000S
D4 = BAT54WS_0: CLABCONF0: = SB-iMX8
F2 = Fuse,_0.75A_Ih,_1.5A_It: CLABCONF0: = SB-iMX8
J2 = HDMI_Connector: CLABCONF0: = SB-iMX8
R2 = 49.9R_1%,_0402_1: CLABCONF0: = SB-iMX8
R4 = 49.9R_1%,_0402_2: CLABCONF0: = SB-iMX8
R6 = 49.9R_1%,_0402_3: CLABCONF0: = SB-iMX8
R8 = 49.9R_1%,_0402_5: CLABCONF0: = SB-iMX8
R9 = 49.9R_1%,_0402_4: CLABCONF0: = SB-iMX8
R10 = 49.9R_1%,_0402_6: CLABCONF0: = SB-iMX8
R11 = 49.9R_1%,_0402_7: CLABCONF0: = SB-iMX8
R12 = 49.9R_1%,_0402: CLABCONF0: = SB-iMX8
R29 R37 = 4_0.75K,1%,0402,1_16W: CLABCONF0: = SB-iMX8
R30 R38 = 4_0.75K,1%,0402,1_16W_1: CLABCONF0: = SB-iMX8
R33 = 4_0.75K,1%,0402,1_16W_2: CLABCONF0: = SB-iMX8
R34 = 4_0.75K,1%,0402,1_16W_3: CLABCONF0: = SB-iMX8
R124 = 33R,5%,0402,1_16W_3: CLABCONF0: = SB-iMX8
R125 = 33R,5%,0402,1_16W_1: CLABCONF0: = SB-iMX8
R127 = 33R,5%,0402,1_16W_6: CLABCONF0: = SB-iMX8
R128 = 33R,5%,0402,1_16W_2: CLABCONF0: = SB-iMX8
R136 = 0R,_0402_1_13: CLABCONF0: = DNP
R138 R162 R217 = 0R,_0402_1: CLABCONF0: = SB-iMX8
R141 = 0R,_0402_1_5: CLABCONF0: = SB-iMX8
R163 = 33R,5%,0402,1_16W_4: CLABCONF0: = SB-iMX8
R164 = 33R,5%,0402,1_16W_5: CLABCONF0: = SB-iMX8
R165 = 33R,5%,0402,1_16W_7: CLABCONF0: = SB-iMX8
R166 = 0R,_0402_1_18: CLABCONF0: = DNP
R167 = 0R,_0402_1_22: CLABCONF0: = DNP
R170 = 0R,_0402_1_24: CLABCONF0: = SB-iMX8
R71 R171 = 0R,_0402_1_1: CLABCONF0: = SB-iMX8
R172 = 33R,5%,0402,1_16W: CLABCONF0: = SB-iMX8
R173 = 0R,_0402_1_6: CLABCONF0: = DNP
R174 = 0R,_0402_1_14: CLABCONF0: = SB-iMX8
R175 = 0R,_0402_1_17: CLABCONF0: = SB-iMX8
R176 = 0R,_0402_1_20: CLABCONF0: = SB-iMX8
R177 = 0R,_0402_1_25: CLABCONF0: = SB-iMX8
R178 = 0R,_0402_1_8: CLABCONF0: = SB-iMX8
R180 = 0R,_0402_1_3: CLABCONF0: = SB-iMX8
R181 = 0R,_0402_1_10: CLABCONF0: = DNP
R182 = 0R,_0402_1_16: CLABCONF0: = SB-iMX8
R183 = 0R,_0402_1_21: CLABCONF0: = SB-iMX8
R184 = 0R,_0402_1_9: CLABCONF0: DNP
R185 = 0R,_0402_1_12: CLABCONF0: DNP
R186 = 0R,_0402_1_7: CLABCONF0: = SB-iMX8
R187 = 0R,_0402_1_19: CLABCONF0: = SB-iMX8
R188 = 0R,_0402_1_26: CLABCONF0: DNP
R189 = 0R,_0402_1_2: CLABCONF0: DNP
R191 = 100K,_1%,_0402,_1_16W: CLABCONF0: = SB-iMX8
R196 = 0R,_0402_1_23: CLABCONF0: = SB-iMX8
R199 = 0R,_0402_1_4: CLABCONF0: = SB-iMX8
R209 = 0R,_0402_1_11: CLABCONF0: = SB-iMX8
R214 = 0R,_0402_1_15: CLABCONF0: =DNP
R64 R228 = 10K,1%,0402,1_16W: CLABCONF0: = SB-iMX8
R54 R169 R230 = 10K,1%,0402,1_16W_1: CLABCONF0: = SB-iMX8
RN17 = RN,10K,8P4R@0805: CLABCONF0: = SB-iMX8
RN20 = RN,4.7K,8P4R@0805: CLABCONF0: = SB-iMX8
U5 U32 = IP4220CZ6_0: CLABCONF0: = SB-iMX8
U31 = PCA9555: CLABCONF0: = SB-iMX8
U36 = IDT5V41066_0: CLABCONF0: = SB-iMX8; P/N: 116A00120S
X2 = XTAL,_25.000Mhz,_3x5mm: CLABCONF0: = SB-iMX8; P/N: 141B25601S
C140-C143 C156 C158 C160 = 10uF,6_0.3V,0603,20%X5R: CLABCONF0: = SB-iMX8
C144 = 100nF,_10V,_X7R,_10%,_0402_14: CLABCONF0: = SB-iMX8
C162 = 100nF,_10V,_X7R,_10%,_0402_15: CLABCONF0: = SB-iMX8
C163 = 100nF,_10V,_X7R,_10%,_0402_17: CLABCONF0: = SB-iMX8
C167 = 100nF,_10V,_X7R,_10%,_0402_16: CLABCONF0: = SB-iMX8
C168 = 100nF,_10V,_X7R,_10%,_0402_18: CLABCONF0: = SB-iMX8
F4-F6 = Fuse,_0.75A_Ih,_1.5A_It: CLABCONF0: = SB-iMX8; P/N: 175P22200S
J4 = USB3_TYPEA_CONNECTER: CLABCONF0: = SB-iMX8; Manuf: MainSuper; Manuf PN: AK2SA009K1; PART_NUMBER: DS PORT2; TI_Silktext: DS PORT2
L24-L32 L42-L46 = ESD_CHOKE_DIFFx2_10: CLABCONF0: = SB-iMX8; P/N: 142D11801S
R5 = 6.04k,1%,0402,1_16W: CLABCONF0: = SB-iMX8
R7 = 5.11k,_%1: CLABCONF0: = SB-iMX8
R15 = 200R,1%,0402,1_16W: CLABCONF0: = SB-iMX8
R143 = 10K,1%,0402,1_16W_11: CLABCONF0: = SB-iMX8
R68 R144 = 10K,1%,0402,1_16W_2: CLABCONF0: = SB-iMX8
R145 = 10K,1%,0402,1_16W_7: CLABCONF0: = SB-iMX8
R146 = 10K,1%,0402,1_16W: CLABCONF0: DNP
R147 = 1K,1%,0402,1_16W_1: CLABCONF0: = SB-iMX8; Group: CAN
R148 = 0R,_0402_1_1: CLABCONF0: = DNP
R149 = 10K,1%,0402,1_16W_6: CLABCONF0: DNP
R150 = 10K,1%,0402,1_16W_8: CLABCONF0: = SB-iMX8
R151 = 10K,1%,0402,1_16W_10: CLABCONF0: = SB-iMX8
R152 = 10K,1%,0402,1_16W_5: CLABCONF0: = SB-iMX8
R153 = 10K,1%,0402,1_16W_9: CLABCONF0: = SB-iMX8
R155 = 10K,1%,0402,1_16W_3: CLABCONF0: = SB-iMX8
R156 = 1K,1%,0402,1_16W: CLABCONF0: DNP; Group: CAN
R158 = 10K,1%,0402,1_16W_4: CLABCONF0: DNP
R168 R198 = 0R,_0402_1: CLABCONF0: DNP
TP1-TP3 = TESTPOINT: CLABCONF0: = SB-iMX8
U27 = CYUSB3304_4: CLABCONF0: = SB-iMX8; P/N: 116A00280S; Color: Default; Location X-Coordinate: 0; Location Y-Coordinate: 0; Power Pins Visible: False; Primitive: DEFAULT
U28 = RT9186A,LDO_,2.5-5_0.5V,500mA: CLABCONF0: = SB-iMX8
U30 = USB3-TYPEA-DUAL_,TH: CLABCONF0: = SB-iMX8; P/N: 180K02202
X1 = XTAL,_25.000Mhz,_3x5mm: CLABCONF0: = SB-iMX8; P/N: 141B26600S
C50 = 220pF,50V,NPO,0603: CLABCONF0: = SB-iMX8
C51 = 10nF,_25V,_X7R,_10%,_0402: CLABCONF0: = SB-iMX8
C52 = 100pF,_50V,_NPO,_5%,_0402: CLABCONF0: = SB-iMX8
C53 = 10nF,_25V,_X7R,_10%,_0402_1: CLABCONF0: = SB-iMX8
JP8 JP11 JP13 = Jumper,_black,_100mil: CLABCONF0: = SB-iMX8
JP12 = Jumper,_black,_100mil: CLABCONF0: DNP
P5 = AUDIO_JACK_3.5mm,_no_sw.,_SMT: CLABCONF0: = SB-iMX8
P6 P7 = Audio_JACK,_STEREO+AUX+SW_3.5mm: CLABCONF0: = SB-iMX8
P20 P21 = HDR_2x17_100MIL_SMT: CLABCONF0: = SB-iMX8
P29 = HDR_2x5_100MIL_TH: CLABCONF0: = SB-iMX8; Group: COM2
R31 = 4_0.75K,1%,0402,1_16W: CLABCONF0: DNP
R32 = 4_0.75K,1%,0402,1_16W_1: CLABCONF0: DNP
R63 = 47K,_0402_1: CLABCONF0: = SB-iMX8; P/N: 161C68001S
R65 = 47K,_0402: CLABCONF0: = SB-iMX8
R66 = 100R,1%,0402,1_16W: CLABCONF0: = SB-iMX8
R67 = 220R,5%,0402,1_16W: CLABCONF0: = SB-iMX8
R69 = 100R,1%,0402,1_16W_2: CLABCONF0: = SB-iMX8
R70 = 100R,1%,0402,1_16W_1: CLABCONF0: = SB-iMX8
R72 = 0R,_0402_1_2: CLABCONF0: = SB-iMX8
R161 = 0R,_0402_1_3: CLABCONF0: = DNP
SW4-SW6 = TACT_SW_6x6mm_SMT: CLABCONF0: = SB-iMX8
U29 = 74LCX04_sgl_gate_TSSOP-14: CLABCONF0: = SB-iMX8
C178 = 1uF,16V,0402: CLABCONF0: = SB-iMX8
E17 = HDR_1x3_100MIL_TH_JUMPER: CLABCONF0: = SB-iMX8
J5 = CON5: CLABCONF0: = SB-iMX8; P/N: 182E00500S
J6 = CON6: CLABCONF0: = SB-iMX8; P/N: 182P00600
P18 = FPC_20_0: CLABCONF0: = SB-iMX8; P/N: 182K02002S
R192 = 0R,_0402_5: CLABCONF0: DNP
R193 = 10K,1%,0402,1_16W_0: CLABCONF0: = SB-iMX8
R194 = 10K,1%,0402,1_16W_0_1: CLABCONF0: = SB-iMX8
R195 = 0R,_0402_7: CLABCONF0: DNP
R201 = 0R,_0402_8: CLABCONF0: = SB-iMX8
R207 = 0R,_0402_0: CLABCONF0: DNP; P/N: 161C00005S
R216 = 0R,_0402: CLABCONF0: = SB-iMX8
R218 = 0R,_0402_2: CLABCONF0: = SB-iMX8
R219 = 0R,_0402_3: CLABCONF0: = SB-iMX8
R220 = 0R,_0402_6: CLABCONF0: = SB-iMX8
R221 = 0R,_0402_4: CLABCONF0: = SB-iMX8
C36 = Cap.,10uF,6.3V,0603,X5R_1: CLABCONF0: = SB-iMX8
C39 = Cap.,10uF,6.3V,0603,X5R: CLABCONF0: DNP
C126 = 22uF,25V,_0805_1: CLABCONF0: DNP
C128 = 22uF,25V,_0805: CLABCONF0: DNP
J11 = Conn.,_PCIEx1,_SMT: CLABCONF0: DNP; P/N: 182K03601S
R197 = 10K,1%,0402,1_16W: CLABCONF0: = DNP
R200 = 0R,_0402_1_1: CLABCONF0: DNP
H7-H10 = Mechanical_Hole: CLABCONF0: = DNP
H12 = Hole,_Plated,_M2,_5mm._ext.: CLABCONF0: = DNP
SCREW1 = SCREW,_M2,_3.5mm,_PAN_HEAD: CLABCONF0: = SB-iMX8
SP10 SP21 SP22 = SMT_SPACER_M2x3: CLABCONF0: = SB-iMX8
SPACER1 = Hexagonal_Standoff_0: CLABCONF0: = DNP; P/N: 206C10160

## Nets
1V2_EN: R168.1 R169.2 U28.4(EN)
1V2_FB: R7.2 R145.1 U28.6(ADJ)
1V2_PER: C140.1 C143.1 C148.1 C149.1 C150.1 C151.1 R7.1 U27.1(DVDD12_2) U27.3(DVDD12_6) U27.7(DVDD12_4) U27.10(AVDD12_1) U27.13(DVDD12_1) U27.16(AVDD12_2) U27.19(VDD_EFUSE) U27.27(DVDD12_3) U27.34(AVDD12_3) U27.37(DVDD12_5) U27.43(DVDD12_7) U27.46(AVDD12_4) U27.49(DVDD12_8) U27.52(AVDD12_5) U27.53(AVDD12_6) U28.7(Vout1) U28.8(Vout2)
1V2_PGOOD: R148.2 U28.3(PGOOD)
3V3_AW: C193.1 P21.7 R33.1 R34.1 R136.2 R166.2 R167.2 SW6.1 SW6.3 U31.21(VDD) ; also on sheet 11 12
3V3_PER: C36.1 C39.1 C142.1 C144.1 C145.1 C146.1 C147.1 E17.1 FB3.1 J11.A9(+3.3V) J11.A10(+3.3V) J11.B8(+3.3V) J11.B10(3.3Vaux) P21.6 P29.2 R31.1 R32.1 R37.1 R38.1 R143.2 R144.2 R150.2 R151.2 R152.2 R153.1 R155.2 R195.2 R197.2 R228.2 R230.2 RN20.6(RC2) RN20.7(RB2) U27.4(AVDD33_1) U27.28(VDD_IO) U27.56(AVDD33_2) U27.61(AVDD33_3) U27.66(AVDD33_4) U29.14(VCC) U36.1(VDDXD) ; also on sheet 10 11 12
5V0_HDMI: F2.2 J2.18(+5V) R29.2 R30.2 U5.5(VBUS)
5V0_HDMI_FUSED: D4.CATHODE F2.1
5V0_PER: C37.1 C38.1 C156.1 C157.1 C158.1 C159.1 C160.1 C161.1 D4.ANODE E17.3 F4.2 F5.2 F6.2 P21.12 R147.2 R156.2 R169.1 R192.1 U27.17(VBUS__US) U27.18(VBUS__DS) U28.1(Vin1) U28.2(Vin2) ; also on sheet 10 12
AGND: P1.195(AUDIO_GND) R71.2
AVDD33_ETH: P1.2(3V3A_ETH_PHY)
GND: C1.2 C2.2 C3.2 C4.2 C5.2 C6.2 C7.2 C8.2 C9.2 C10.2 C11.2 C12.2 C13.2 C14.2 C15.2 C16.2 C17.2 C18.2 C19.2 C20.2 C23.2 C36.2 C37.2 C38.2 C39.2 C43.1 C47.2 C105.2 C126.2 C128.2 C139.2 C140.2 C141.2 C142.2 C143.2 C144.2 C145.2 C146.2 C147.2 C148.2 C149.2 C150.2 C151.2 C154.1 C155.1 C156.2 C157.2 C158.2 C159.2 C160.2 C161.2 C166.2 C169.1 C178.2 C185.1 C186.1 C193.2 FB1.2 H7.1 H8.1 H9.1 H10.1 H12.1 J2.2(D2_Shield) J2.5(D1_Shield) J2.8(D0_Shield) J2.11(CK_Shield) J2.17(GND) J2.20(SHELL1) J2.21(SHELL2) J4.4(GND) J4.7(GND) J4.SH1 J4.SH2 J5.2 J11.A4(GND) J11.A12(GND) J11.A15(GND) J11.A18(GND) J11.B4(GND) J11.B7(GND) J11.B13(GND) J11.B16(GND) J11.B18(GND) L24.5(GND) L24.6(GND) L25.5(GND) L25.6(GND) L26.5(GND) L26.6(GND) L27.5(GND) L27.6(GND) L28.5(GND) L28.6(GND) L29.5(GND) L29.6(GND) L30.5(GND) L30.6(GND) L31.5(GND) L31.6(GND) L32.5(GND) L32.6(GND) L42.5(GND) L42.6(GND) L43.5(GND) L43.6(GND) L44.5(GND) L44.6(GND) L45.5(GND) L45.6(GND) L46.5(GND) L46.6(GND) P1.1(GND1) P1.19(GND2) P1.37(GND3) P1.55(GND4) P1.71(GND5) P1.87(GND6) P1.105(GND7) P1.123(GND8) P1.141(GND9) P1.159(GND10) P1.177(GND11) P18.3 P18.4 P18.7 P18.10 P18.13 P18.16 P18.19 P18.20 P20.33 P21.31 P29.4 P29.6 R2.2 R4.2 R5.2 R6.2 R8.2 R9.2 R10.2 R11.2 R12.2 R15.1 R50.2 R51.2 R54.2 R72.1 R121.1 R145.2 R146.1 R149.1 R158.2 R162.1 R191.2 R219.1 RN17.2(RB1) RN17.3(RC1) RN17.4(RD1) RN20.8(RA2) SP10.1 SP21.1 SP22.1 SW4.1 SW4.3 SW5.1 SW5.3 U5.2(GND) U27.40(GND) U28.5(GND) U28.9(EPAD) U29.7(GND) U30.A4(GND1) U30.A7(GND7) U30.B4(GND2) U30.B7(GND8) U30.SH1(SHIELD1) U30.SH2(SHIELD2) U30.SH3(SHIELD3) U30.SH4(SHIELD4) U31.9(VSS) U36.9(GNDXD) U36.16(GNDODA) X1.2 X1.4 X2.2 X2.4 ; also on sheet 10 11 12
V3P3_Q7_PCIECLK_A: C43.2 FB3.2 U36.15(VDDODA)
VCC_RTC: C1.1 P1.183(BACKUP_BAT) ; also on sheet 12
100MHz_CLK_S0: RN20.3(RC1) U36.2(S0)
100MHz_CLK_S1: RN20.2(RB1) U36.3(S1)
100MHz_CLK_SS2: RN20.1(RA1) U36.4(SS2)
100MHz_IREF: R121.2 U36.10(IREF)
100MIL_10K_PD: P21.30 R54.1
A_IN: C53.2 R69.2
ALT_BOOT: P1.185(ALT_BOOT) P21.9 SW6.2 SW6.4
AMP_IN: R68.2 R69.1 U29.3(I)
AMP_OUT: R68.1 U29.1(I) U29.4(12)
AMPR: C49.2 R64.1
AUDIO_IN_DIG: C53.1 P7.2(AUX) P7.CO R70.2
AUDIO_OUT_DIG: C52.1 P6.2(AUX) R66.2 R67.1
BOOT_FLASH_nWP: P1.189(EEPROM_WP) P21.11
CARRIER_3V3_GPIO0_0: R138.2 U31.1(I/O0.0)
CARRIER_3V3_GPIO0_1: R141.2 U31.2(I/O0.1)
CARRIER_3V3_GPIO0_3: R174.2 U31.4(I/O0.3)
CARRIER_3V3_GPIO0_4: R175.2 U31.5(I/O0.4)
CARRIER_3V3_GPIO0_5: R176.2 U31.6(I/O0.5)
CARRIER_3V3_GPIO0_6: R177.2 U31.7(I/O0.6)
CARRIER_3V3_GPIO0_7: R180.2 U31.8(I/O0.7)
CARRIER_3V3_GPIO1_0: R178.2 U31.10(I/O1.0)
CARRIER_3V3_GPIO1_2: R199.2 U31.12(I/O1.2)
CARRIER_3V3_GPIO1_4: R209.2 U31.14(I/O1.4)
CARRIER_3V3_GPIO1_5: R214.2 U31.15(I/O1.5)
CARRIER_3V3_GPIO1_6: R196.2 U31.16(I/O1.6)
CLK_OE: R228.1 U36.8(OE)
CLK_PD#: R230.1 U36.7(PD#)
CONN_AGND: C50.1 C52.2 P5.1(COM) P6.1(COM) P7.1(COM) R65.2 R67.2 R70.1 R71.1 R72.2
CSI_MCLK: R141.1 ; also on sheet 10
CSI_P1_CKN: P1.109(PCAM_DAT9) ; also on sheet 10
CSI_P1_CKP: P1.107(PCAM_DAT8) ; also on sheet 10
CSI_P1_DN0: P1.85(PCAM_DAT7) ; also on sheet 10
CSI_P1_DN1: P1.91(PCAM_DAT3) ; also on sheet 10
CSI_P1_DN2: P1.103(PCAM_DAT1) P20.5
CSI_P1_DN3: P1.113(PCAM_VSYNC) P20.32
CSI_P1_DP0: P1.83(PCAM_DAT6) ; also on sheet 10
CSI_P1_DP1: P1.89(PCAM_DAT2) ; also on sheet 10
CSI_P1_DP2: P1.101(PCAM_DAT0) P20.7
CSI_P1_DP3: P1.115(PCAM_HSYNC) P20.34
CSI_PWR_DWN: R178.1 ; also on sheet 10
CSI_RST: R180.1 ; also on sheet 10
DBG_UART_RXD: P1.117(UARTDBG_RX) ; also on sheet 11
DBG_UART_TXD: P1.111(UARTDBG_TX) ; also on sheet 11
DEBUGSEL: R176.1 ; also on sheet 11
DISP_ADJ: J5.4 R194.2 R201.2 R214.1
DISP_ON: J5.3 R193.2 R199.1
DISP_PWR: C169.2 C185.2 E17.2 P18.1 P18.2 R192.2 R193.1 R194.1 R195.1 R216.1
DISP_RESET: R207.1 R209.1 R221.1
DS1_CON_DN: J4.2(DM) L24.4
DS1_CON_DP: J4.3(DP) L24.3
DS1_CON_RXN: J4.5(SSRXN) L31.4
DS1_CON_RXP: J4.6(SSRXP) L31.3
DS1_CON_TXN: J4.8(SSTXN) L32.3
DS1_CON_TXP: J4.9(SSTXP) L32.4
DS1_DN: L24.1 U27.59(DS1_DN)
DS1_DP: L24.2 U27.60(DS1_DP)
DS1_HUB_TXN: C153.1 U27.48(DS1_TXM)
DS1_HUB_TXP: C152.1 U27.47(DS1_TXP)
DS1_RXN: L31.1 U27.50(DS1_RXM)
DS1_RXP: L31.2 U27.51(DS1_RXP)
DS1_TXN: C153.2 L32.2
DS1_TXP: C152.2 L32.1
DS3_CON_DN: L25.4 U30.B2(D-)
DS3_CON_DP: L25.3 U30.B3(D+)
DS3_DN: L25.1 U27.64(DS3_DN)
DS3_DP: L25.2 U27.65(DS3_DP)
DS3_HUB_TXN: C162.1 U27.39(DS3_TXM)
DS3_HUB_TXP: C163.1 U27.38(DS3_TXP)
DS3_RXN: L27.1 U27.36(DS3_RXM)
DS3_RXN_CONN: L27.4 U30.B5(SSRX2-)
DS3_RXP: L27.2 U27.35(DS3_RXP)
DS3_RXP_CONN: L27.3 U30.B6(SSRX2+)
DS3_TXN: C162.2 L28.1
DS3_TXN_CONN: L28.4 U30.B8(SSTX2-)
DS3_TXP: C163.2 L28.2
DS3_TXP_CONN: L28.3 U30.B9(SSTX2+)
DS4_CON_DN: L26.4 U30.A2(D-)
DS4_CON_DP: L26.3 U30.A3(D+)
DS4_DN: L26.1 U27.68(DS4_DN)
DS4_DP: L26.2 U27.67(DS4_DP)
DS4_HUB_TXN: C164.1 U27.12(DS4_TXM)
DS4_HUB_TXP: C165.1 U27.11(DS4_TXP)
DS4_RXN: L29.1 U27.14(DS4_RXM)
DS4_RXN_CONN: L29.4 U30.A5(SSRX1-)
DS4_RXP: L29.2 U27.15(DS4_RXP)
DS4_RXP_CONN: L29.3 U30.A6(SSRX1+)
DS4_TXN: C164.2 L30.1
DS4_TXN_CONN: L30.4 U30.A8(SSTX1-)
DS4_TXP: C165.2 L30.2
DS4_TXP_CONN: L30.3 U30.A9(SSTX1+)
ECSPI2_MISO/UART4_CTS_B_CM: P1.15(ECSPI2_MISO) P20.9
ECSPI2_MOSI/UART4_TX_CM: P1.11(ECSPI2_MOSI) P21.3
ECSPI2_SCLK/UART4_RX_CM: P1.13(ECSPI2_SCLK) P21.5
ECSPI2_SS0/UART4_RTS_B_CM: P1.17(ECSPI2_SS0) P20.11
ENET_MDC_CM: P1.52(SPI_CS1) P20.1
ENET_TD2_CM: P1.62(GPIO11) P21.1
ETH0_SHIELD: C166.1 FB1.1 P2.S1(SHIELD) P2.S2(SHIELD)
ETH1_CT1: C19.1 C20.1 C23.1 P2.P5(CT) P2.P6(CT)
ETH1_GREEN_LED_CAT: P2.P11(LED1_C) R50.1
ETH1_LED_ACT/PHY1ADDRESS2: P1.4(ETH_LED2_ACT) P2.P12(LED1_A)
ETH1_LINK-LED_10_100: D1.1(ANODE1) P1.22(ETH_LED3)
ETH1_LINK-LED_1000/INTSELECT: D1.2(ANODE2) P1.16(ETH_LED1_SPD)
ETH1_MDI0N: P1.6(MDI0-/TX-) P2.P2(MDI0-)
ETH1_MDI0P: P1.8(MDI0+/TX+) P2.P1(MDI0+)
ETH1_MDI1N: P1.12(MDI1-/RX-) P2.P4(MDI1-)
ETH1_MDI1P: P1.14(MDI1+/RX+) P2.P3(MDI1+)
ETH1_MDI2N: P1.18(MDI2-) P2.P8(MDI2-)
ETH1_MDI2P: P1.20(MDI2+) P2.P7(MDI2+)
ETH1_MDI3N: P1.24(MDI3-) P2.P10(MDI3-)
ETH1_MDI3P: P1.26(MDI3+) P2.P9(MDI3+)
ETH1_YELLOW_LED_AN: D1.3(CATHODE) P2.P14(LED2_A)
ETH1_YELLOW_LED_CAT: P2.P13(LED2_C) R51.1
EXPANDER_A0: R166.1 RN17.5(RD2) U31.18(A0)
EXPANDER_A1: R167.1 RN17.6(RC2) U31.23(A1)
EXPANDER_A2: R136.1 RN17.7(RB2) U31.24(A2)
FPC_GND: J6.3 R219.2 U32.2(GND)
FPC_INT: J6.2 R220.2 U32.3(IO2)
FPC_PWR: C186.2 J6.6 R216.2 U32.5(VBUS)
FPC_RES: J6.1 R221.2 U32.1(IO1)
FPC_SCL: J6.4 R218.2 U32.4(IO3)
FPC_SDA: J6.5 R217.2 U32.6(IO4)
HDMI_AUXN: P1.27(HDMI_AUXN) P21.15
HDMI_AUXP: P1.29(HDMI_AUXP) P21.17
HDMI_CEC/ETH2_LINK-LED_10_100: J2.13(CE_Remote) P1.34(HDMI_CEC)
HDMI_CLKN/ETH2_MDI0P: J2.12(CK-) P1.32(TMDS_CLK-)
HDMI_CLKP/ETH2_MDI0N: J2.10(CK+) P1.30(TMDS_CLK+)
HDMI_DDC_SCL/ETH2_LED_ACT/PHY2ADDR2: J2.15(DDC_CLK) P1.25(TMDS_DDC_SCL) R30.1 U5.6(IO4)
HDMI_DDC_SDA: J2.16(DDC_DATA) P1.31(TMDS_DDC_SDA) R29.1 U5.4(IO3)
HDMI_HPD/ETH2_LINK-LED_1000/INTSELECT: J2.19(HP_DET) P1.40(TMDS_HPD) R191.1 U5.1(IO1)
HDMI_TXN0/ETH2_MDI1P: J2.9(D0-) P1.38(TMDS_DAT0-)
HDMI_TXN1/ETH2_MDI2P: J2.6(D1-) P1.44(TMDS_DAT1-)
HDMI_TXN2/ETH2_MDI3P: J2.3(D2-) P1.50(TMDS_DAT2-)
HDMI_TXP0/ETH2_MDI1N: J2.7(D0+) P1.36(TMDS_DAT0+)
HDMI_TXP1/ETH2_MDI2N: J2.4(D1+) P1.42(TMDS_DAT1+)
HDMI_TXP2/ETH2_MDI3N: J2.1(D2+) P1.48(TMDS_DAT2+)
HUB_MODE_SEL0: R149.2 R151.1 U27.23(MODE_SEL[0])
HUB_MODE_SEL1: R146.2 R150.1 U27.24(MODE_SEL[1])
HUB_OVRCURR: R153.2 R158.1 U27.30(OVRCURR)
HUB_PWREN: R155.1 R174.1 U27.29(PWR_EN)
HUB_RESETN: C141.1 R148.1 R152.1 R175.1 U27.31(RESETN)
HUB_XTALI_26M: C155.2 U27.55(XTL_IN) X1.3
HUB_XTALO_26M: C154.2 U27.54(XTL_OUT) X1.1
HUBCLK: TP1.1 U27.32(I2C_CLK)
HUBDATA: TP2.1 U27.33(I2C_DATA)
HUBRSV1: R144.1 U27.21(RESERVED1)
HUBRSV2: R143.1 U27.22(RESERVED2)
HUBSUS: TP3.1 U27.20(SUSPEND)
I2C1_SCL: P1.129(I2C3_SCL) R33.2 R198.2 U31.19(SCL) ; also on sheet 10 11
I2C1_SDA: P1.135(I2C3_SDA) R34.2 R200.2 U31.20(SDA) ; also on sheet 10 11
I2C3_SCL/PWM4_OUT: P1.43(I2C2_SCL) R38.2 R218.1
I2C3_SDA/PWM3_OUT: P1.49(I2C2_SDA) R37.2 R217.1
I2C4_SCL/PWM2_OUT: P1.73(PWM) P20.6 R31.2 R201.1
I2C4_SDA/PWM1_OUT: P1.75(GPIO3) P20.8 R32.2
IDT_CLK0_N: R127.1 U36.19(CLK0_N)
IDT_CLK0_P: R124.1 U36.20(CLK0_P)
IDT_CLK1_N: R128.1 U36.17(CLK1_N)
IDT_CLK1_P: R125.1 U36.18(CLK1_P)
IDT_CLK2_N: R164.1 U36.13(CLK2_N)
IDT_CLK2_P: R163.1 U36.14(CLK2_P)
IDT_CLK3_N: R172.1 U36.11(CLK3_N)
IDT_CLK3_P: R165.1 U36.12(CLK3_P)
IDT_CLK_X1: C105.1 U36.5(X1/ICLK) X2.1
IDT_CLK_X2: C47.1 U36.6(X2) X2.3
IDT_T_CLK0_N: R4.1 R127.2 R171.2
IDT_T_CLK0_P: R2.1 R124.2 R170.2
IDT_T_CLK1_N: R8.1 R128.2 R183.2
IDT_T_CLK1_P: R6.1 R125.2 R182.2
IDT_T_CLK2_N: R10.1 R164.2 R185.2
IDT_T_CLK2_P: R9.1 R163.2 R184.2
IDT_T_CLK3_N: R12.1 R172.2 R189.2
IDT_T_CLK3_P: R11.1 R165.2 R188.2
JTAG_HDR_10: P29.10 R161.2 R162.2
JTAG_MOD: P1.54(GPIO8) P21.28
JTAG_nTRST: P1.56(GPIO9) R161.1
JTAG_TCK: P1.66(RTOUCH_X+) P29.3
JTAG_TDI: P1.70(RTOUCH_Y+) P29.7
JTAG_TDO: P1.72(RTOUCH_Y-) P29.5
JTAG_TMS: P1.68(RTOUCH_X-) P29.1
LHPOUT: P1.203(ANALOG_LOUT) P6.4(L)
LLINEIN: P1.199(ANALOG_LIN) P7.4(L)
LVDS0_CLK_N: L46.3 P1.35(LVDS_CLK0-)
LVDS0_CLK_P: L46.4 P1.33(LVDS_CLK0+)
LVDS0_CLKN: L46.2 P18.14
LVDS0_CLKP: L46.1 P18.15
LVDS0_N0: L42.2 P18.5
LVDS0_N1: L43.2 P18.8
LVDS0_N2: L44.2 P18.11
LVDS0_N3: L45.2 P18.17
LVDS0_P0: L42.1 P18.6
LVDS0_P1: L43.1 P18.9
LVDS0_P2: L44.1 P18.12
LVDS0_P3: L45.1 P18.18
LVDS0_TX0_N: L42.3 P1.41(LVDS_TX0-)
LVDS0_TX0_P: L42.4 P1.39(LVDS_TX0+)
LVDS0_TX1_N: L43.3 P1.47(LVDS_TX1-)
LVDS0_TX1_P: L43.4 P1.45(LVDS_TX1+)
LVDS0_TX2_N: L44.3 P1.53(LVDS_TX2-)
LVDS0_TX2_P: L44.4 P1.51(LVDS_TX2+)
LVDS0_TX3_N: L45.3 P1.59(LVDS_TX3-)
LVDS0_TX3_P: L45.4 P1.57(LVDS_TX3+)
LVDS1_CLK_N: P1.79(PCAM_DAT5) P21.21
LVDS1_CLK_P: P1.77(PCAM_DAT4) P21.19
LVDS1_TX0_N: P1.23(LVDS1_TX0_N) P21.22
LVDS1_TX0_P: P1.21(LVDS1_TX0_P) P21.20
LVDS1_TX1_N: P1.95(PCAM_PCLK) P21.25
LVDS1_TX1_P: P1.93(PCAM_STROBE) P21.23
LVDS1_TX2_N: P1.99(PCAM_RESET) P21.26
LVDS1_TX2_P: P1.97(PCAM_WEN) P21.24
LVDS1_TX3_N: P1.163(GPIO5) P21.29
LVDS1_TX3_P: P1.161(GPIO4) P21.27
MIC_IN: C49.1 C50.2 P5.2(L) R63.2 R65.1
MICBIAS: P1.191(ANALOG_MICBIAS/MICIN+) R63.1
MICIN: P1.193(ANALOG_MICIN/MICIN-) R64.2
mPCIE1_REF_CLKN: R171.1 R181.2 ; also on sheet 10
mPCIE1_REF_CLKP: R170.1 R173.2 ; also on sheet 10
mPCIe_PERST: R138.1 ; also on sheet 10
NAND_CLE/QSPI_B_SCLK: P1.147(SDIO_CMD) P20.18
NAND_DATA4/QSPI_B_DATA0: P1.155(SDIO_DAT0) P20.26
NAND_DATA5/QSPI_B_DATA1: P1.153(SDIO_DAT1) P20.24
NAND_DATA6/QSPI_B_DATA2: P1.151(SDIO_DAT2) P20.22
NAND_DATA7/QSPI_B_DATA3: P1.149(SDIO_DAT3) P20.20
NAND_nCE2/QSPI_B_SS0_B: P1.7(QSPI_B_SS0) P21.32
NAND_nCE3/QSPI_B_SS1_B: P1.9(QSPI_B_SS1) P21.34
NAND_nRE/QSPI_B_DQS: P1.157(SDIO_CLK) P20.28
NAND_nWE: P1.60(GPIO10) U31.22(\\~{IN}T)
NAND_nWP: P1.81(PCAM_SHUTTER) P20.3
P1-74_PDISP_DATA22: P1.74(PDISP_DAT22)
P1-76_PDISP_DATA23: P1.76(PDISP_DAT23)
P1-92_PDISP_DATA17: P1.92(PDISP_DAT17)
P1-94_PDISP_DATA16: P1.94(PDISP_DAT16)
P1-98_PDISP_PCLK: P1.98(PDISP_PCLK)
P1-100_PDISP_HSYNC: P1.100(PDISP_HSYNC)
P1-102_PDISP_VSYNC: P1.102(PDISP_VSYNC)
P1-104_PDISP_DE: P1.104(PDISP_DE)
P1-106_PDISP_DATA00: P1.106(PDISP_DAT0)
P1-108_PDISP_DATA01: P1.108(PDISP_DAT1)
P1-110_PDISP_DATA02: P1.110(PDISP_DAT2)
P1-112_PDISP_DATA03: P1.112(PDISP_DAT3)
P1-116_PDISP_DATA04: P1.116(PDISP_DAT4)
P1-118_PDISP_DATA05: P1.118(PDISP_DAT5)
P1-120_PDISP_DATA06: P1.120(PDISP_DAT6)
P1-122_PDISP_DATA07: P1.122(PDISP_DAT7)
P1-124_PDISP_DATA08: P1.124(PDISP_DAT8)
P1-126_PDISP_DATA09: P1.126(PDISP_DAT9)
P1-128_PDISP_DATA10: P1.128(PDISP_DAT10)
P1-130_PDISP_DATA11: P1.130(PDISP_DAT11)
P1-134_PDISP_DATA12: P1.134(PDISP_DAT12)
P1-136_PDISP_DATA13: P1.136(PDISP_DAT13)
P1-138_PDISP_DATA14: P1.138(PDISP_DAT14)
P1-140_PDISP_DATA15: P1.140(PDISP_DAT15)
P1-142_PDISP_DATA18: P1.142(PDISP_DAT18)
P1-144_PDISP_DATA19: P1.144(PDISP_DAT19)
P1-146_PDISP_DATA20: P1.146(PDISP_DAT20)
P1-148_PDISP_DATA21: P1.148(PDISP_DAT21)
PCIE1_REF_CLKN: P1.121(PCIE_REFCLK-) R181.1 R183.1
PCIE1_REF_CLKP: P1.119(PCIE_REFCLK+) R173.1 R182.1
PCIE1_RXN_N: P1.133(PCIE_RX-) ; also on sheet 10
PCIE1_RXN_P: P1.131(PCIE_RX+) ; also on sheet 10
PCIE1_TXN_N: P1.127(PCIE_TX-) ; also on sheet 10
PCIE1_TXN_P: P1.125(PCIE_TX+) ; also on sheet 10
PCIE2_REF_CLKN_CM: P1.179(RESERVED2) R187.1 R189.1
PCIE2_REF_CLKP_CM: P1.181(RESERVED3) R186.1 R188.1
PCIE2_RXN_CM: J11.A17(HSIn(0)) P1.167
PCIE2_RXP_CM: J11.A16(HSIp(0)) P1.169
PCIE2_TXN_CM: J11.B15(HSOn(0)) P1.173
PCIE2_TXP_CM: J11.B14(HSOp(0)) P1.175
PCIEx1_PERST: J11.A11(PERST#) R196.1 R197.1
PCIEx1_REF_CLKN: J11.A14(REFCLK-) R185.1 R187.2
PCIEx1_REF_CLKP: J11.A13(REFCLK+) R184.1 R186.2
PMIC_ON_REQ: P1.202(PER_PWREN_REQ) P20.4 R168.2 ; also on sheet 10 12
PMIC_STBY_REQ: P1.187(nRESET_WARM) P21.13
POR_B: P1.171(COLD_RESET_IN) P20.30 P29.9 R207.2 SW5.2 SW5.4
PWRBTN: P1.165(PWRON) P20.31 SW4.2 SW4.4
RHPOUT: P1.201(ANALOG_ROUT) P6.3(R)
RLINEIN: P1.197(ANALOG_RIN) P7.3(R)
RREF_SS: R15.2 U27.26(RREF_SS)
RREF_USB2: R5.1 U27.2(RREF_USB2)
RS485_CTRL: R177.1 ; also on sheet 11
SAI1_RXC: P1.192(RESERVED4) P20.27
SAI1_RXD4: P1.137(I2S1_CLKX) P20.10
SAI1_RXD5: P1.139(I2S1_DOUT) P20.12
SAI1_RXD6: P1.145(I2S1_FSX) P20.16
SAI1_RXD7: P1.152(GPIO1) P20.23
SAI1_TXD4: P1.194(GPIO6) P20.29
SAI1_TXD5: P1.143(I2S1_DIN) P20.14
SAI1_TXD6: P1.162(USB_nOVC) P20.25
SD2_CLK: P1.80(SDCARD_CLK) ; also on sheet 11
SD2_CMD: P1.82(SDCARD_CMD) ; also on sheet 11
SD2_DATA0: P1.84(SDCARD_DAT0) ; also on sheet 11
SD2_DATA1: P1.86(SDCARD_DAT1) ; also on sheet 11
SD2_DATA2: P1.88(SDCARD_DAT2) ; also on sheet 11
SD2_DATA3: P1.90(SDCARD_DAT3) ; also on sheet 11
SD2_nCD: P1.61(SDCARD_CD) ; also on sheet 11
SD2_nRST: P1.154(GPIO2) P20.13
SD2_WP: P1.67(SDCARD_WP) ; also on sheet 11
SM_CLK: J11.B5(SMCLK) R198.1
SM_DAT: J11.B6(SMDAT) R200.1
SPDIF_EXT_CLK: P1.200(GPIO7) P20.2
SPDIF_OUT1C: C51.1 R66.1
SPDIF_RX: P1.198(PER_PWREN_OUT) U29.2(12)
SPDIF_TX: C51.2 P1.196(BOOT_PWR_IN)
UART1_RXD: P20.21 ; also on sheet 11
UART1_RXD/ECSPI3_SCLK: P1.69(SPI_CLK) ; also on sheet 11
UART1_TXD: P20.19 ; also on sheet 11
UART1_TXD/ECSPI3_MOSI: P1.65(SPI_SIMO) ; also on sheet 11
UART2_RXD/ECSPI3_MISO: P1.63(SPI_SOMI)
UART2_TXD/ECSPI3_SS0: P1.58(SPI_CS0) R220.1
UART4_RXD: P1.5(UART4_RX) P20.17
UART4_TXD: P1.3(UART4_TX) P20.15
USB1_DN: P1.178(HSUSB0_D-) ; also on sheet 10
USB1_DP: P1.176(HSUSB0_D+) ; also on sheet 10
USB1_HOST_VBUS: F4.1 J4.1(VBUS)
USB1_ID: P1.174(USBOTG_ID) ; also on sheet 10
USB1_RX_N: P1.184(SSUSB_RX-) ; also on sheet 10
USB1_RX_P: P1.182(SSUSB_RX+) ; also on sheet 10
USB1_TX_N: P1.190(SSUSB_TX-) ; also on sheet 10
USB1_TX_P: P1.188(SSUSB_TX+) ; also on sheet 10
USB1_VBUS_DET: P1.180(USBOTG_VBUS) R156.1 ; also on sheet 10
USB2_DN: P1.170(HSUSB1_D-) U27.58(US_DN)
USB2_DN2: U27.63(DS2_DN) ; also on sheet 10
USB2_DP: P1.172(HSUSB1_D+) U27.57(US_DP)
USB2_DP2: U27.62(DS2_DP) ; also on sheet 10
USB2_RX_N: C168.1 P1.160(HSUSB3_D+)
USB2_RX_N_C: C168.2 U27.5(US_TXM)
USB2_RX_P: C167.1 P1.158(HSUSB3_D-)
USB2_RX_P_C: C167.2 U27.6(US_TXP)
USB2_TX_N: P1.166(HSUSB2_D+) U27.8(US_RXM)
USB2_TX_P: P1.164(HSUSB2_D-) U27.9(US_RXP)
USB2_VBUS_DET: P1.156(USB_PWREN) R147.1 ; also on sheet 10
USB_VCC3: F5.1 U30.B1(VBUS)
USB_VCC4: F6.1 U30.A1(VBUS)
V_SOM: C2.1 C3.1 C4.1 C5.1 C6.1 C7.1 C8.1 C9.1 C10.1 C11.1 C12.1 C13.1 C14.1 C15.1 C16.1 C17.1 C18.1 C139.1 P1.10(VSYS1) P1.28(VSYS2) P1.46(VSYS3) P1.64(VSYS4) P1.78(VSYS5) P1.96(VSYS6) P1.114(VSYS7) P1.132(VSYS8) P1.150(VSYS9) P1.168(VSYS10) P1.186(VSYS11) P1.204(VSYS12) ; also on sheet 10 12
V_SOM_EN: P21.33 ; also on sheet 12
VDC_IN: C126.1 C128.1 C178.1 J5.1 J11.A2(+12V) J11.A3(+12V) J11.B1(+12V) J11.B2(+12V) ; also on sheet 12
VSB_1V8: P21.18 ; also on sheet 10

Not connected (* = marked no-connect by the designer): FID1 1*; FID2 1*; FID3 1*; FID4 1*; FID5 1*; FID6 1*; J2 14(NC)*; J5 5*; J11 A1(PRSNT#1)* A5(JTAG2)* A6(JTAG3)* A7(JTAG4)* A8(JTAG5)* B3(RSVD0)* B9(JTAG1)* B11(WAKE#)* B12(RSVD1)* B17(PRSNT#2)* X1* X2*; P5 3(R)*; P6 CN* CO*; P7 CN*; P21 2* 4* 8* 10* 14* 16*; P29 8*; RN17 1(RA1)* 8(RA2)*; RN20 4(RD1)* 5(RD2)*; U5 3(IO2)*; U27 25(NC)* 41(DS2_TXP)* 42(DS2_TXM)* 44(DS2_RXM)* 45(DS2_RXP)*; U31 3(I/O0.2)* 11(I/O1.1)* 13(I/O1.3)* 17(I/O1.7)*

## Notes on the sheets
sheet 1
- PCIe X1 SLOT
- PCIe x1 12V RAIL
  peak current = 0.5A
- PCIe x1 3.3V RAIL
  peak current = 3A
- DNP
- DNP
- DNP
- DNP
- DNP
- DNP
- DNP
sheet 2
- LVDS LCD
- DNP
- DNP
- 12V_BACKLIGHT
- I2C for touchscreen
- I2C addres:0xBA/0xBB or 0x28/0x29
  D. Sheet, page 9
- DNP
sheet 3
- SODIMM SPACERS
- mPCIe SPACER
- DNP
- SB-iMX8 SPACERS
sheet 4
- SB-iMX8
- BOARD REVISION: 1.1
- PAGE
- FUNCTION
- 01
- INDEX & BLOCK DIAGRAM
- 02
- CARRIER BOARD INTERFACE
- 03
- ETHERNET
- 04
- HDMI, GPIO EXP, PCIe CLK
- 05
- USB HUB
- 06
- 100 MIL CONN, AUDIO
- 07
- CSI, USB OTG, mPCIE
- 08
- SD, RS232, RS485, EEPROM
- 09
- POWER
- 10
- LVDS LCD, TS CONN, BACKLIGHT CONN
- 11
- PCIe X1 SLOT
- 12
- Mechanics
- I2C ADDRESSES
- DEVICE
- ADDRESS
- EEPROM
- 0x54..57
- GPIO EXT
- 0x20
sheet 5
- CARIER SODIMM INTERFACE
- 100 mill hdr
- 100 mill hdr
- 100 mill hdr
- 100 mill hdr
- lvds conn
- lvds conn
- ts
- ts
- ts
- ts
- PLCD PWM/I2C
- I2C
- SB-SOM I2C
- SAI6_TXC/RXC
- SB-SOM I2C
- SAI6_TXD/RXD
- SAI6_RXD/TXD
- SAI6_TX/RX_SYNC
- SAI6_MCLK
- VBUS2 PWR EN
- SAI6_RX/TX_SYNC
- SAI6_RXC/TXC
sheet 6
- ETHERNET 1
- 100 Ohm
- 100 Ohm
- 100 Ohm
- 100 Ohm
- Layout notes
  1: 100ohm differential impedance control.
  2: Match each differential signals pair ± 5 mils.
  3: Not more than two vias on each differential trace
  4: GND stitching VIA near every signal VIA
  5: The spacing between differential pair signals and other signals should be at least three times the trace width.
sheet 7
- HDMI (8M)
- PCIe CLK
- Make trace to VDD AsShortAsPossible,
  decoupling caps and FB can be placed on back
  and placed ACAP to VDD
- 100MHz clk
- 100 MHzCLK diff pairs
  100 ohm impedance
  28 mil intralane missmatch
- 100 Ohm
- 100 Ohm
- 100 Ohm
- 100 Ohm
- DNP
- IDT
- CP
- SOC
- CP
- IDT
- CP
- SOC
- CP
- DNP
- IDT
- IDT
- DNP
- IDT
- CP
- SOC
- CP
- IDT
- DNP
- CP
- SOC
- CP
- DNP
- IDT
- IDT
- DNP
- PCIe1 is connected to mini PCIe.
  The clock generator generates Mini PCIe's ref clock and iMX8's PCIe1 ref clock (in SOM-iMX8)
  PCIe2 is connected to WLAN (if assembled) in SOM-iMX8 or to PCIe X1 Slot.
  In SOM-iMX8 REV 1.1: iMX8’s clock output provides PCIe2 REF CLK to iMX8 and in addition to that
                       provides ref clock to WLAN (if assembled) or to PCIe X1 Slot.
  In SOM-iMX8 REV 1.0: The clock generator also generates PCIe X1 Slot’s ref clock and iMX8's
                       PCIe2 ref clock (in SOM-iMX8)
- GPIO EXPANDER
- DNP
- I2C address: 0x20
sheet 8
- USB HUB (8M)
- new part
- 100 ohm
- 100 ohm
- 100 ohm
- 100 ohm
- 90 ohm
- 90 ohm
- 90 ohm
- 90 ohm
- 90 ohm
- DNP
- 90 ohm
- 100 ohm
- 100 ohm
- DNP
- 90 ohm
- 90 ohm
- 100 ohm
- 100 ohm
- 100 ohm
- 100 ohm
- 100 ohm
- 100 ohm
- 100 ohm
- 100 ohm
- 100 ohm
- 90 ohm
- 90 ohm
- 100 ohm
- 100 ohm
- 100 ohm
- 100 ohm
- 100 ohm
- 100 ohm
- DNP
- DNP
- 1V2@360mA
- new part
- 3V3@190mA
- Vout=Vfb*(1+Rt/Rb)=0.8*(1+5.11/10)=1.2V
sheet 9
- MIC IN
- AUDIO OUT
- POWER/RESET/BOOT SWITCHES & JTAG
- AUDIO IN
- NXP refdes layout
- TCK
- TMS
- GND
- VCC
- TDO
- GND
- TDI
- nRST
- DNP
- NOT CP
- Keep analog signals clear from other signals at least 30mills
  Analog signals list will be provided in separate doc
- 100mil CONN 1
- Signals can be swaped freely
- 100mil CONN 2
- Signals can be swaped freely
  except jumper dependent like
  alt_boot
- alt_boot jumper
- EPPROM protect jumper
- JTAG_MOD jumper
- DNP
- Layout notes for PCIe and LVDS signals
  1: 100ohm differential impedance control for LVDS, 85ohm for PCIe.
  2: Match each differential signals pair ± 5 mils.
  3: Not more than two vias on each differential trace
  4: GND stitching VIA near every signal VIA
  5: The spacing between differential pair signal and other signals should at least three times the trace width.
- DNP
